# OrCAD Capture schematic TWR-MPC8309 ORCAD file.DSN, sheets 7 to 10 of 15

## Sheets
7 P07:ETH PHYs & RJ45: size C; title: ETH PHYs & RJ45
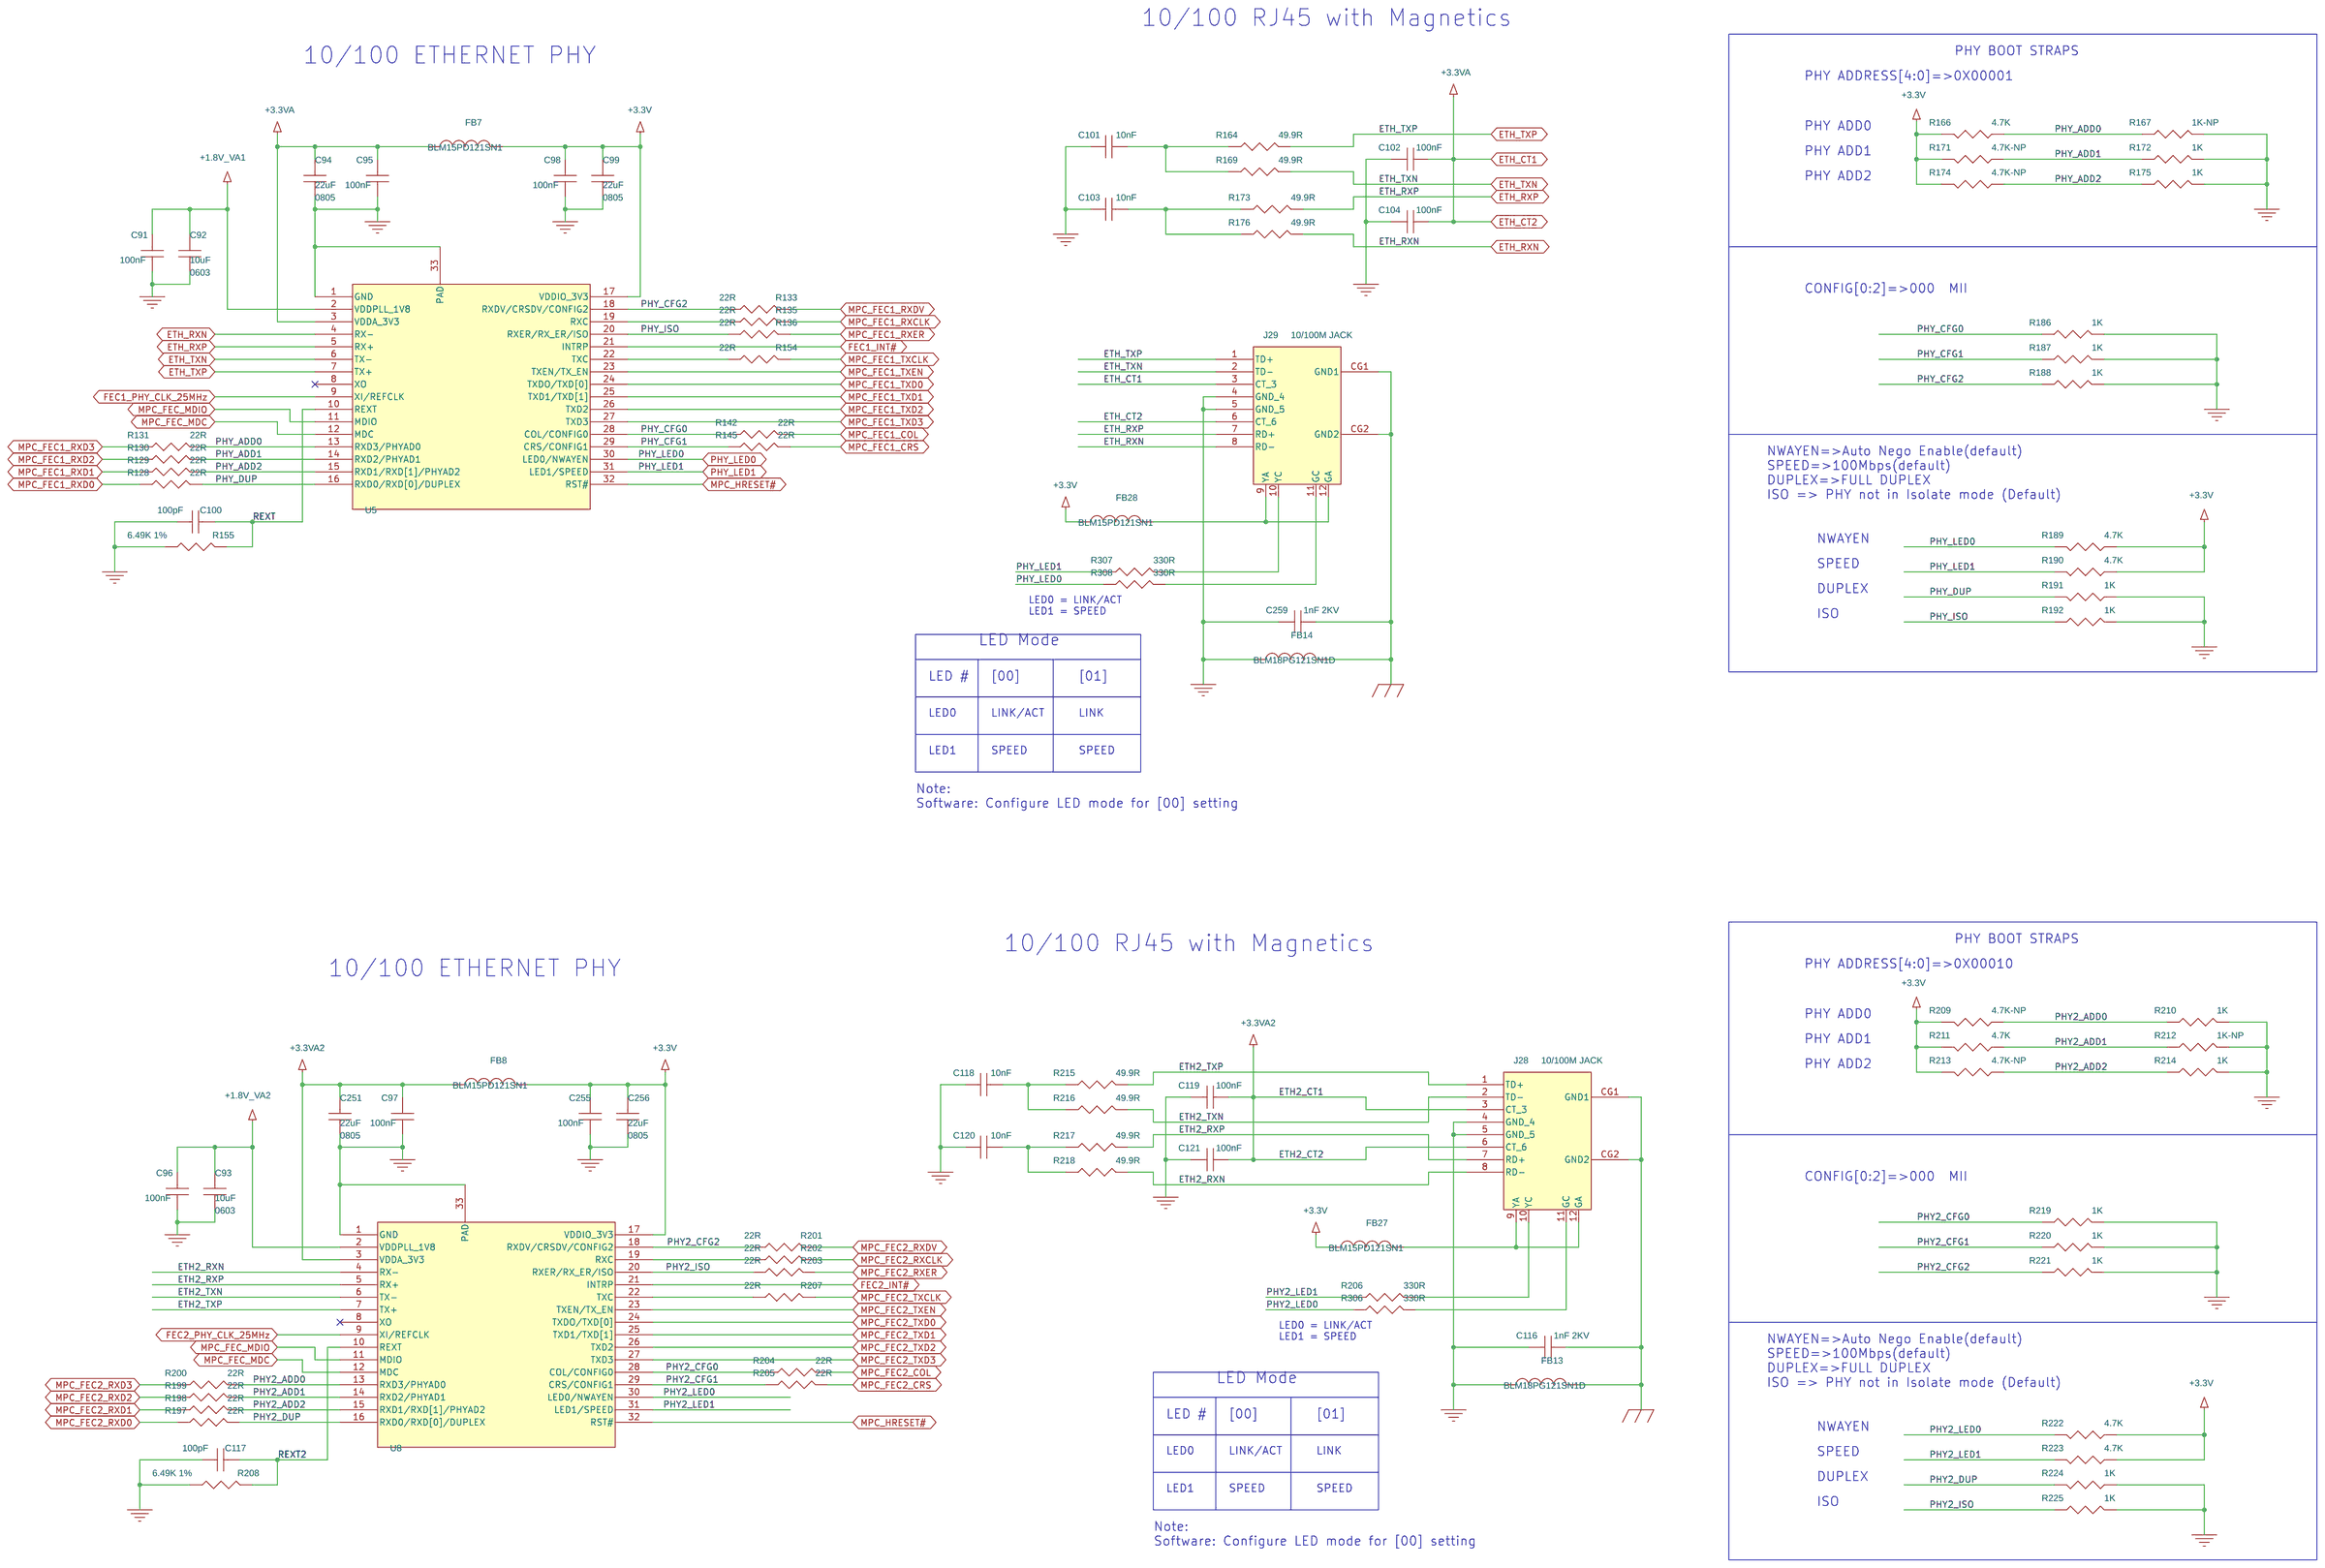
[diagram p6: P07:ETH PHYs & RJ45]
8 P02:Reset, Clock & Switch: size C; title: Reset, Clock and Switch
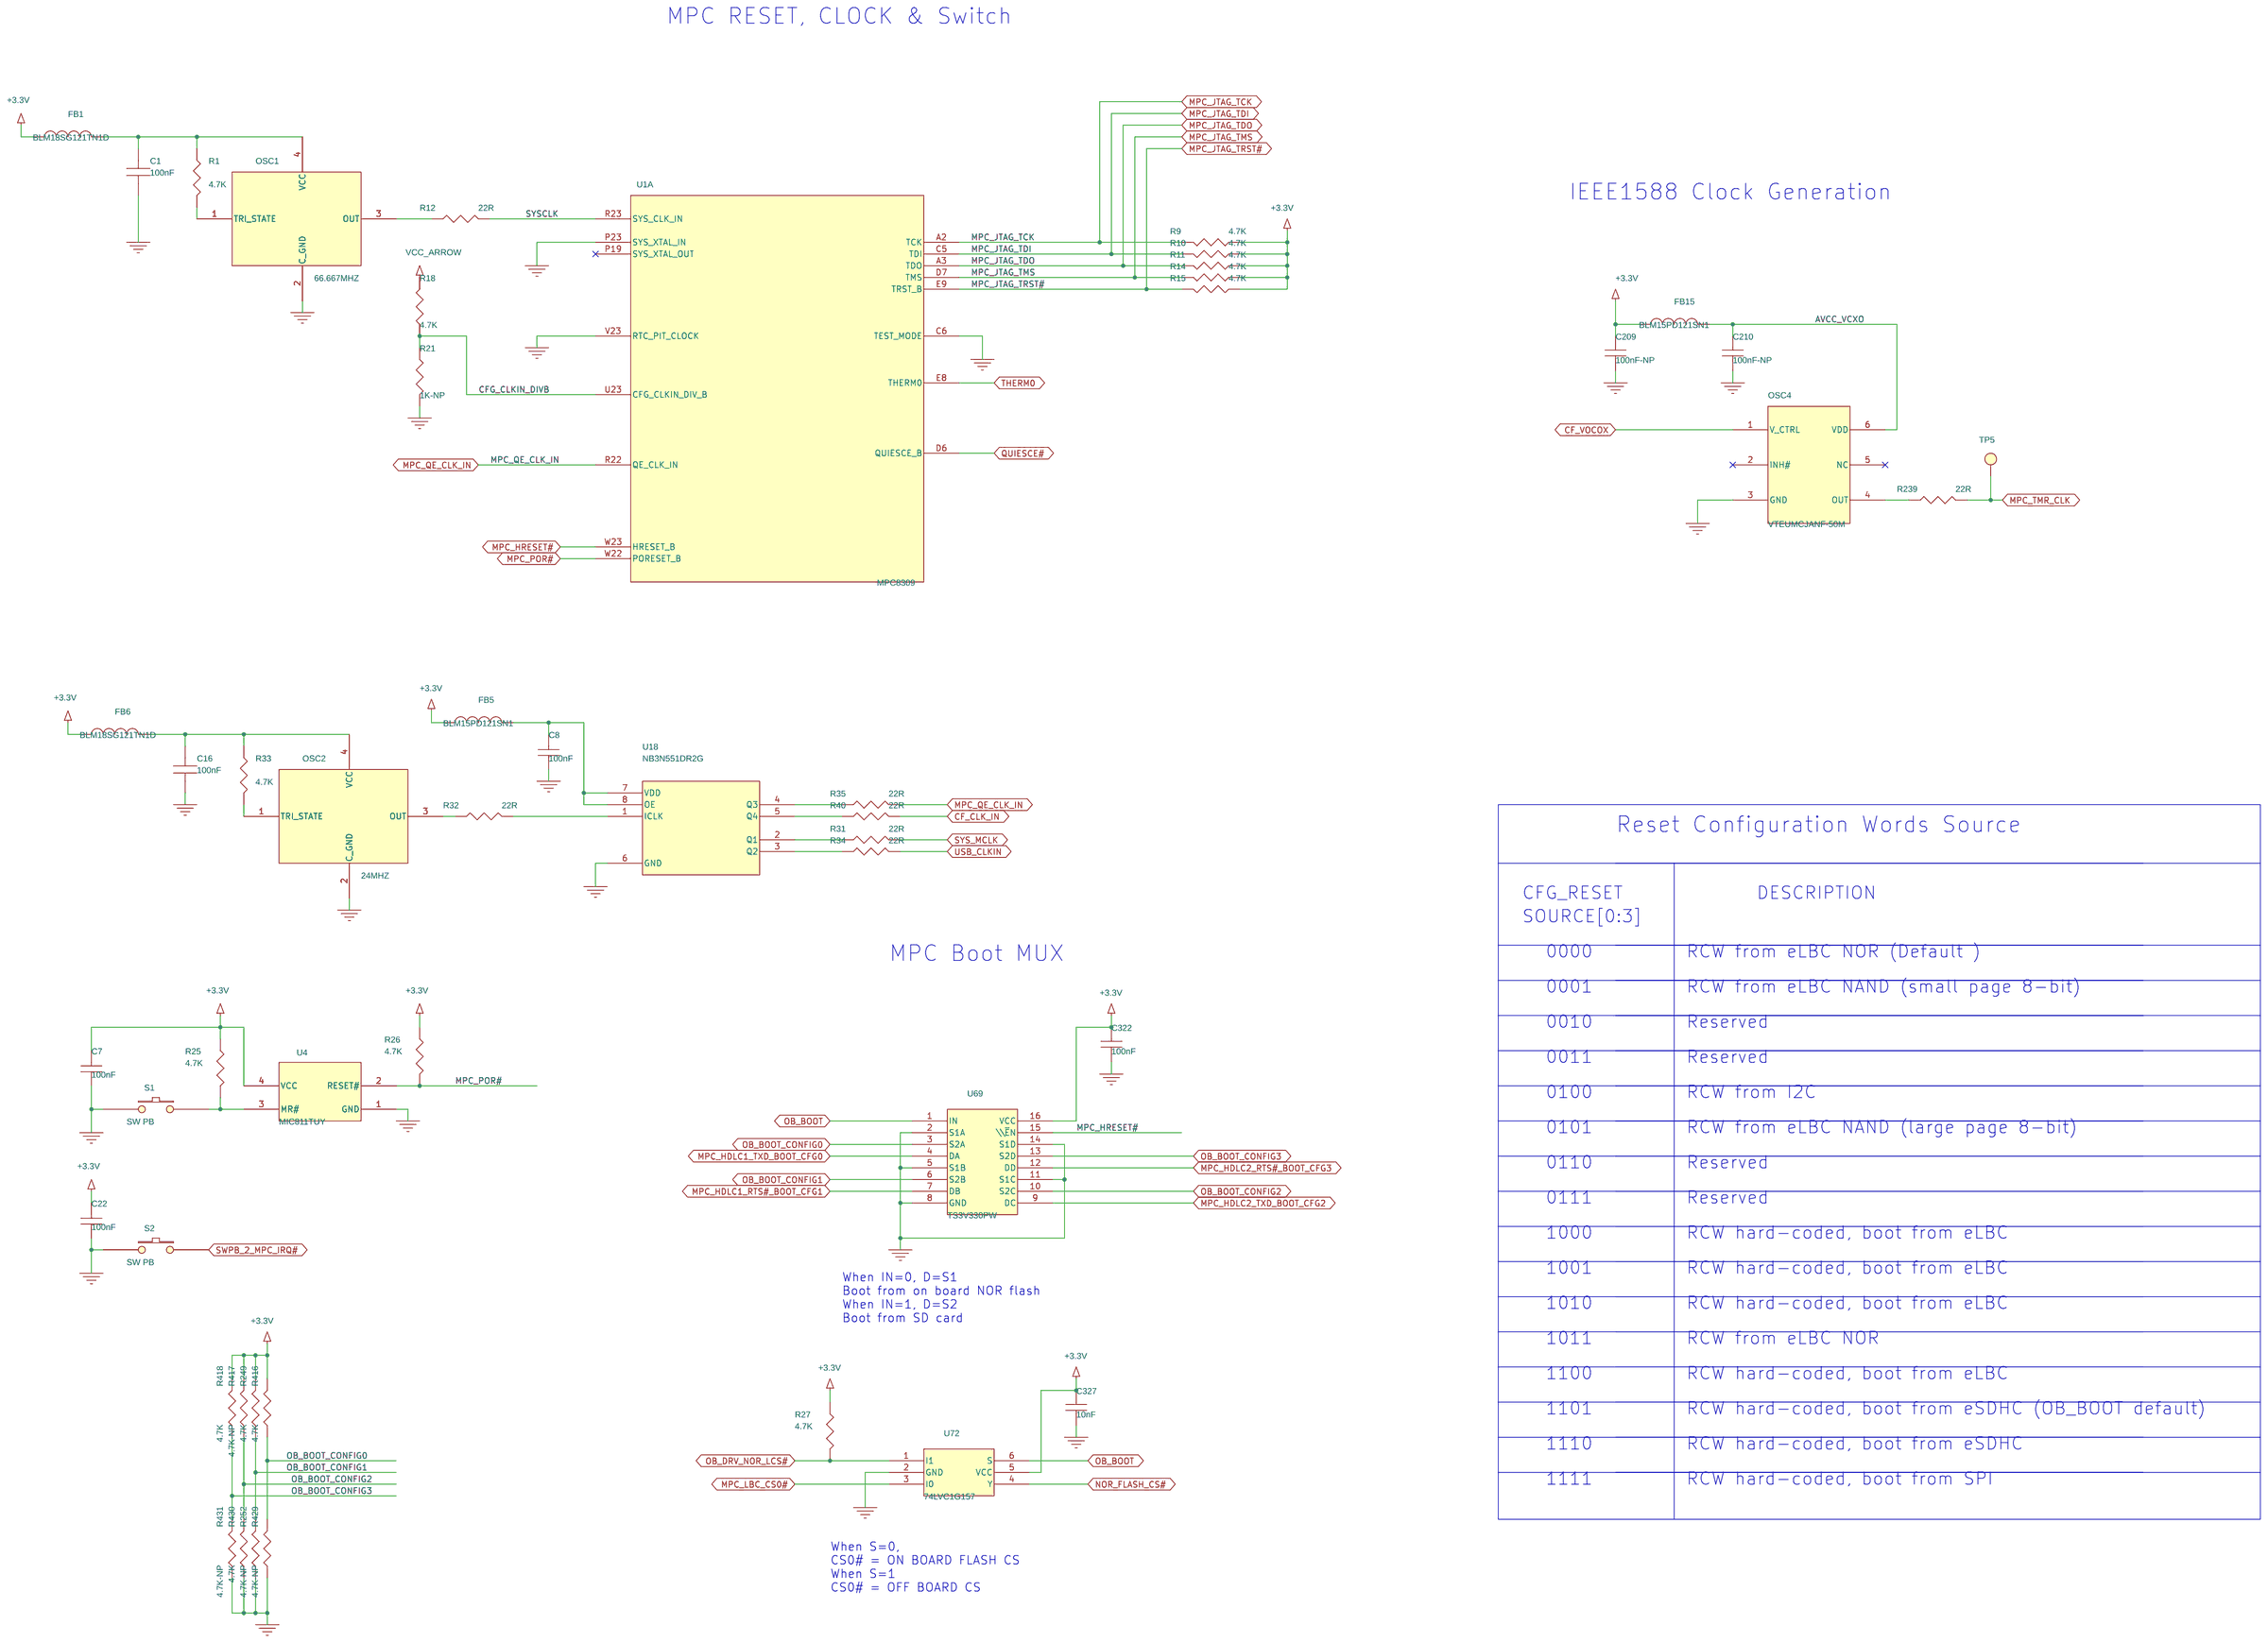
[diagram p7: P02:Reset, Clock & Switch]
9 P08:USB Interface & USB PHY: size C; title: USB Interface and USB PHY
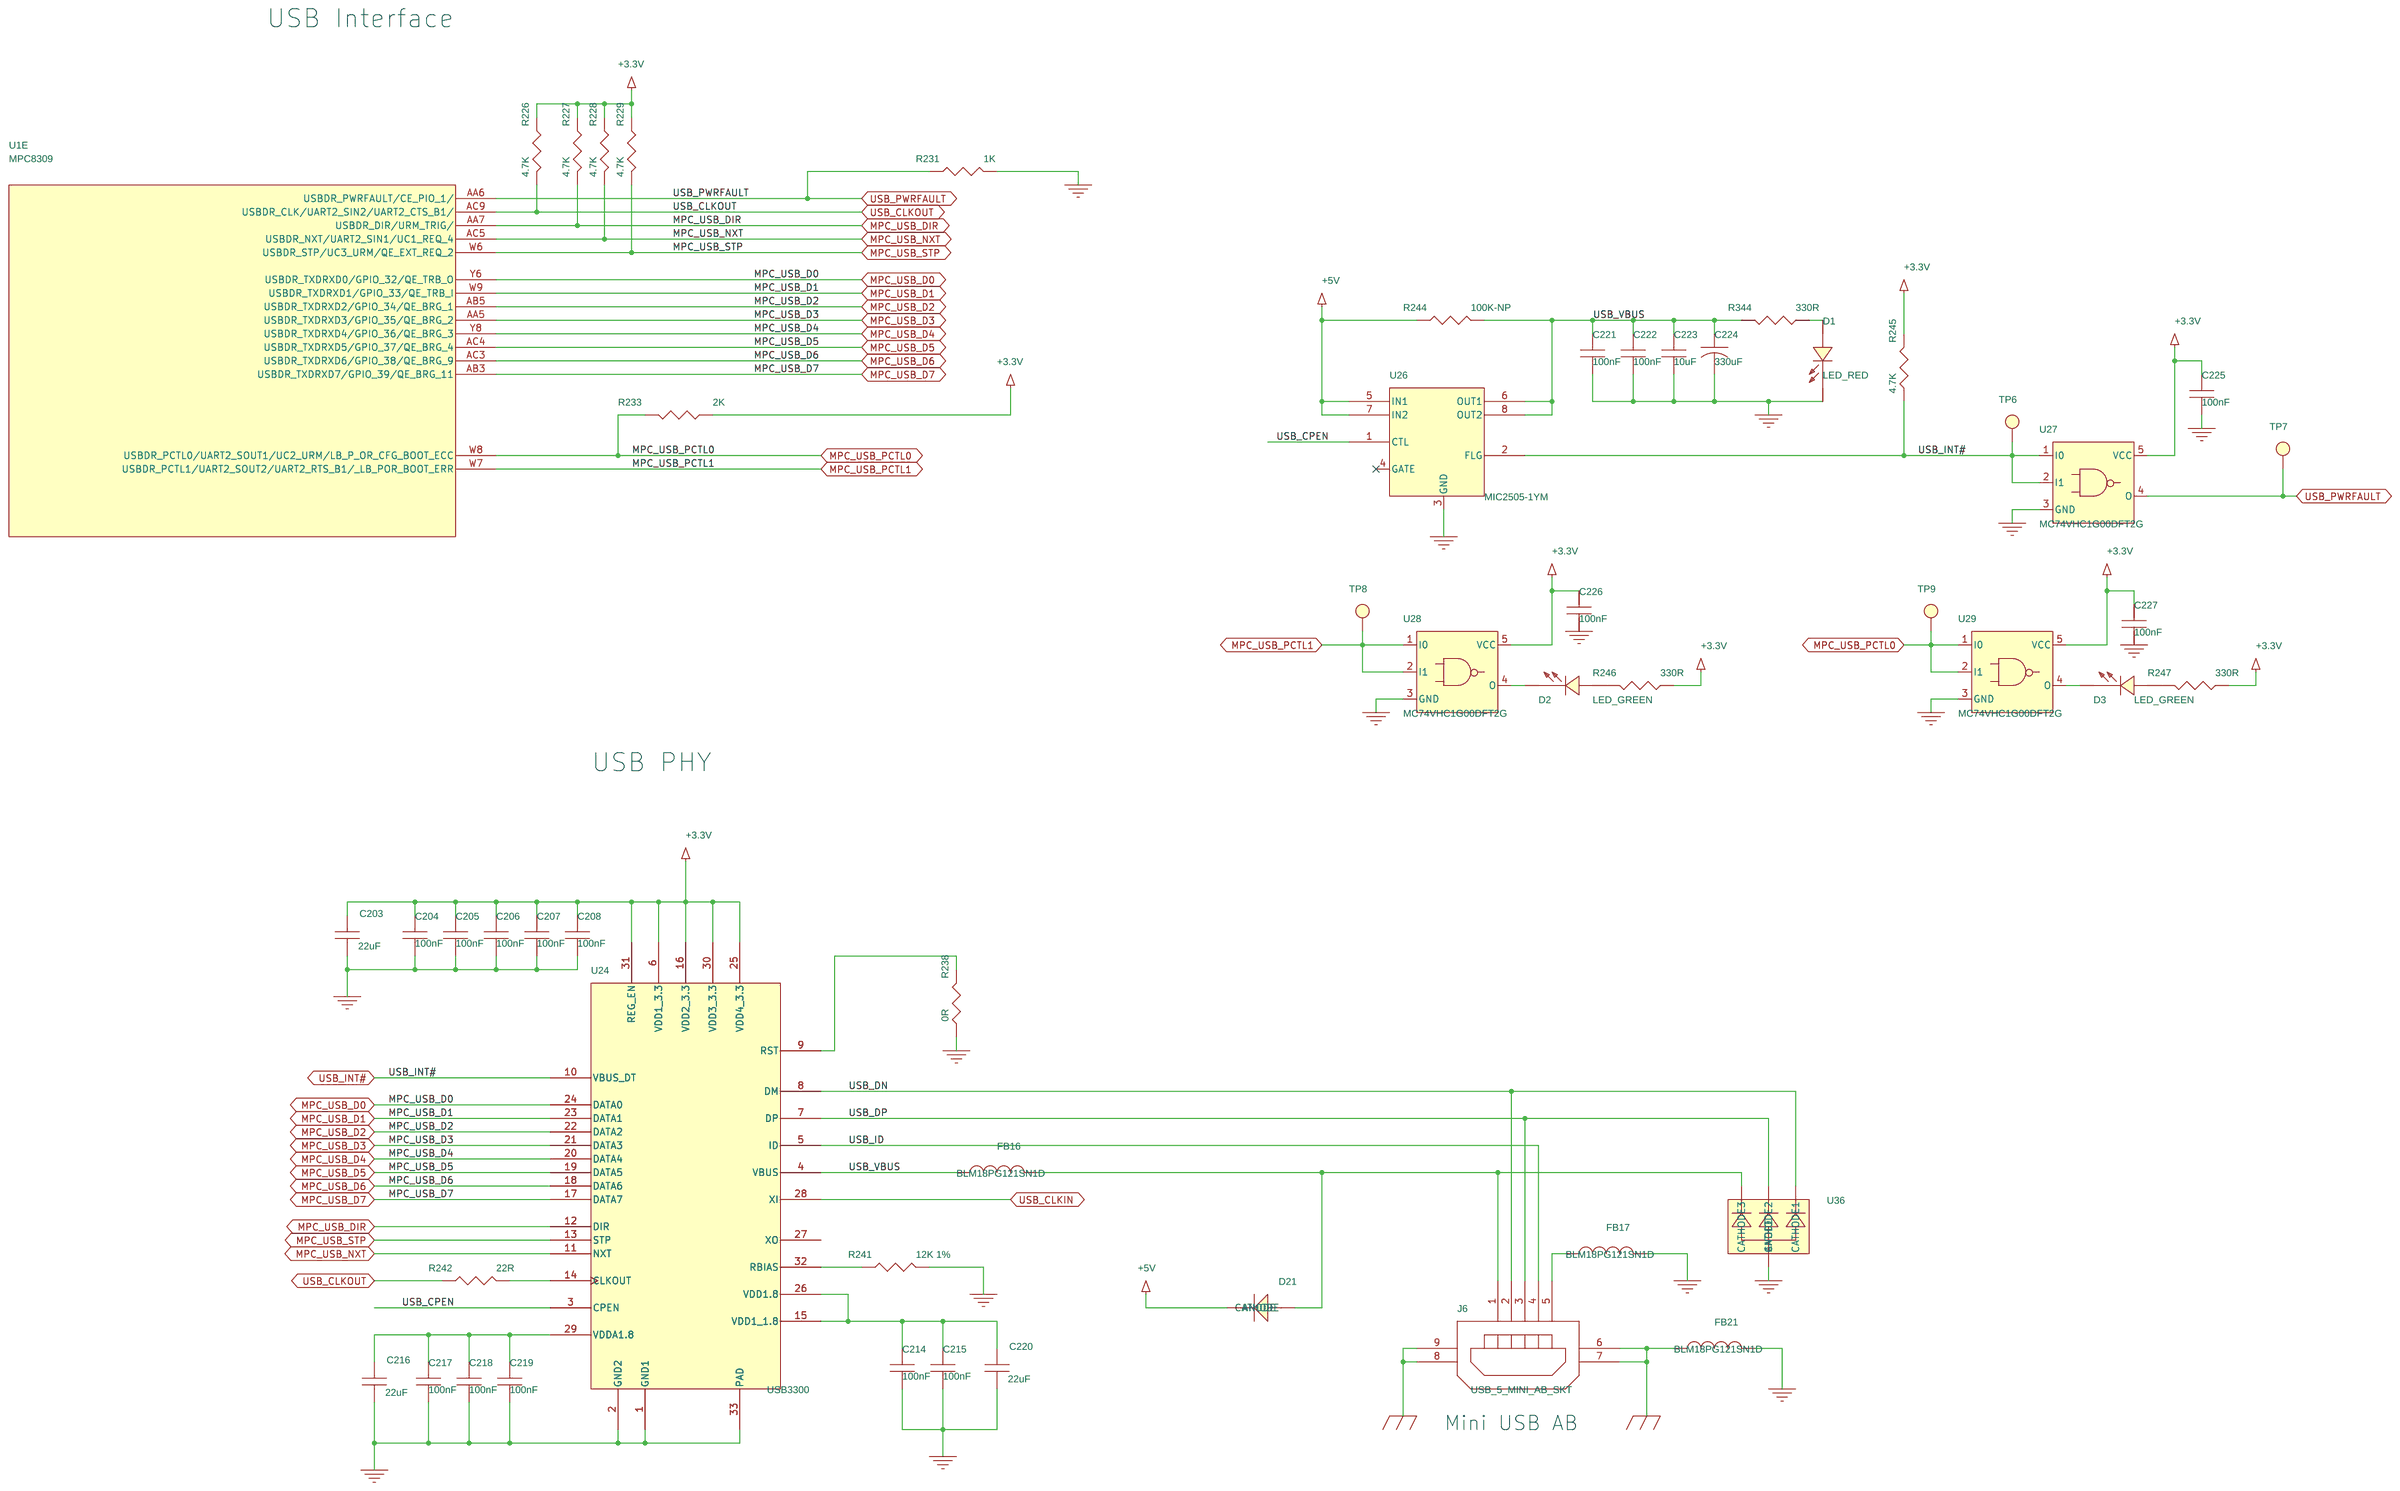
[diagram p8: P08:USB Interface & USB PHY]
10 P03:DDR2 & NOR Flash Memory: size C; title: DDR2 and NOR Flash Memory
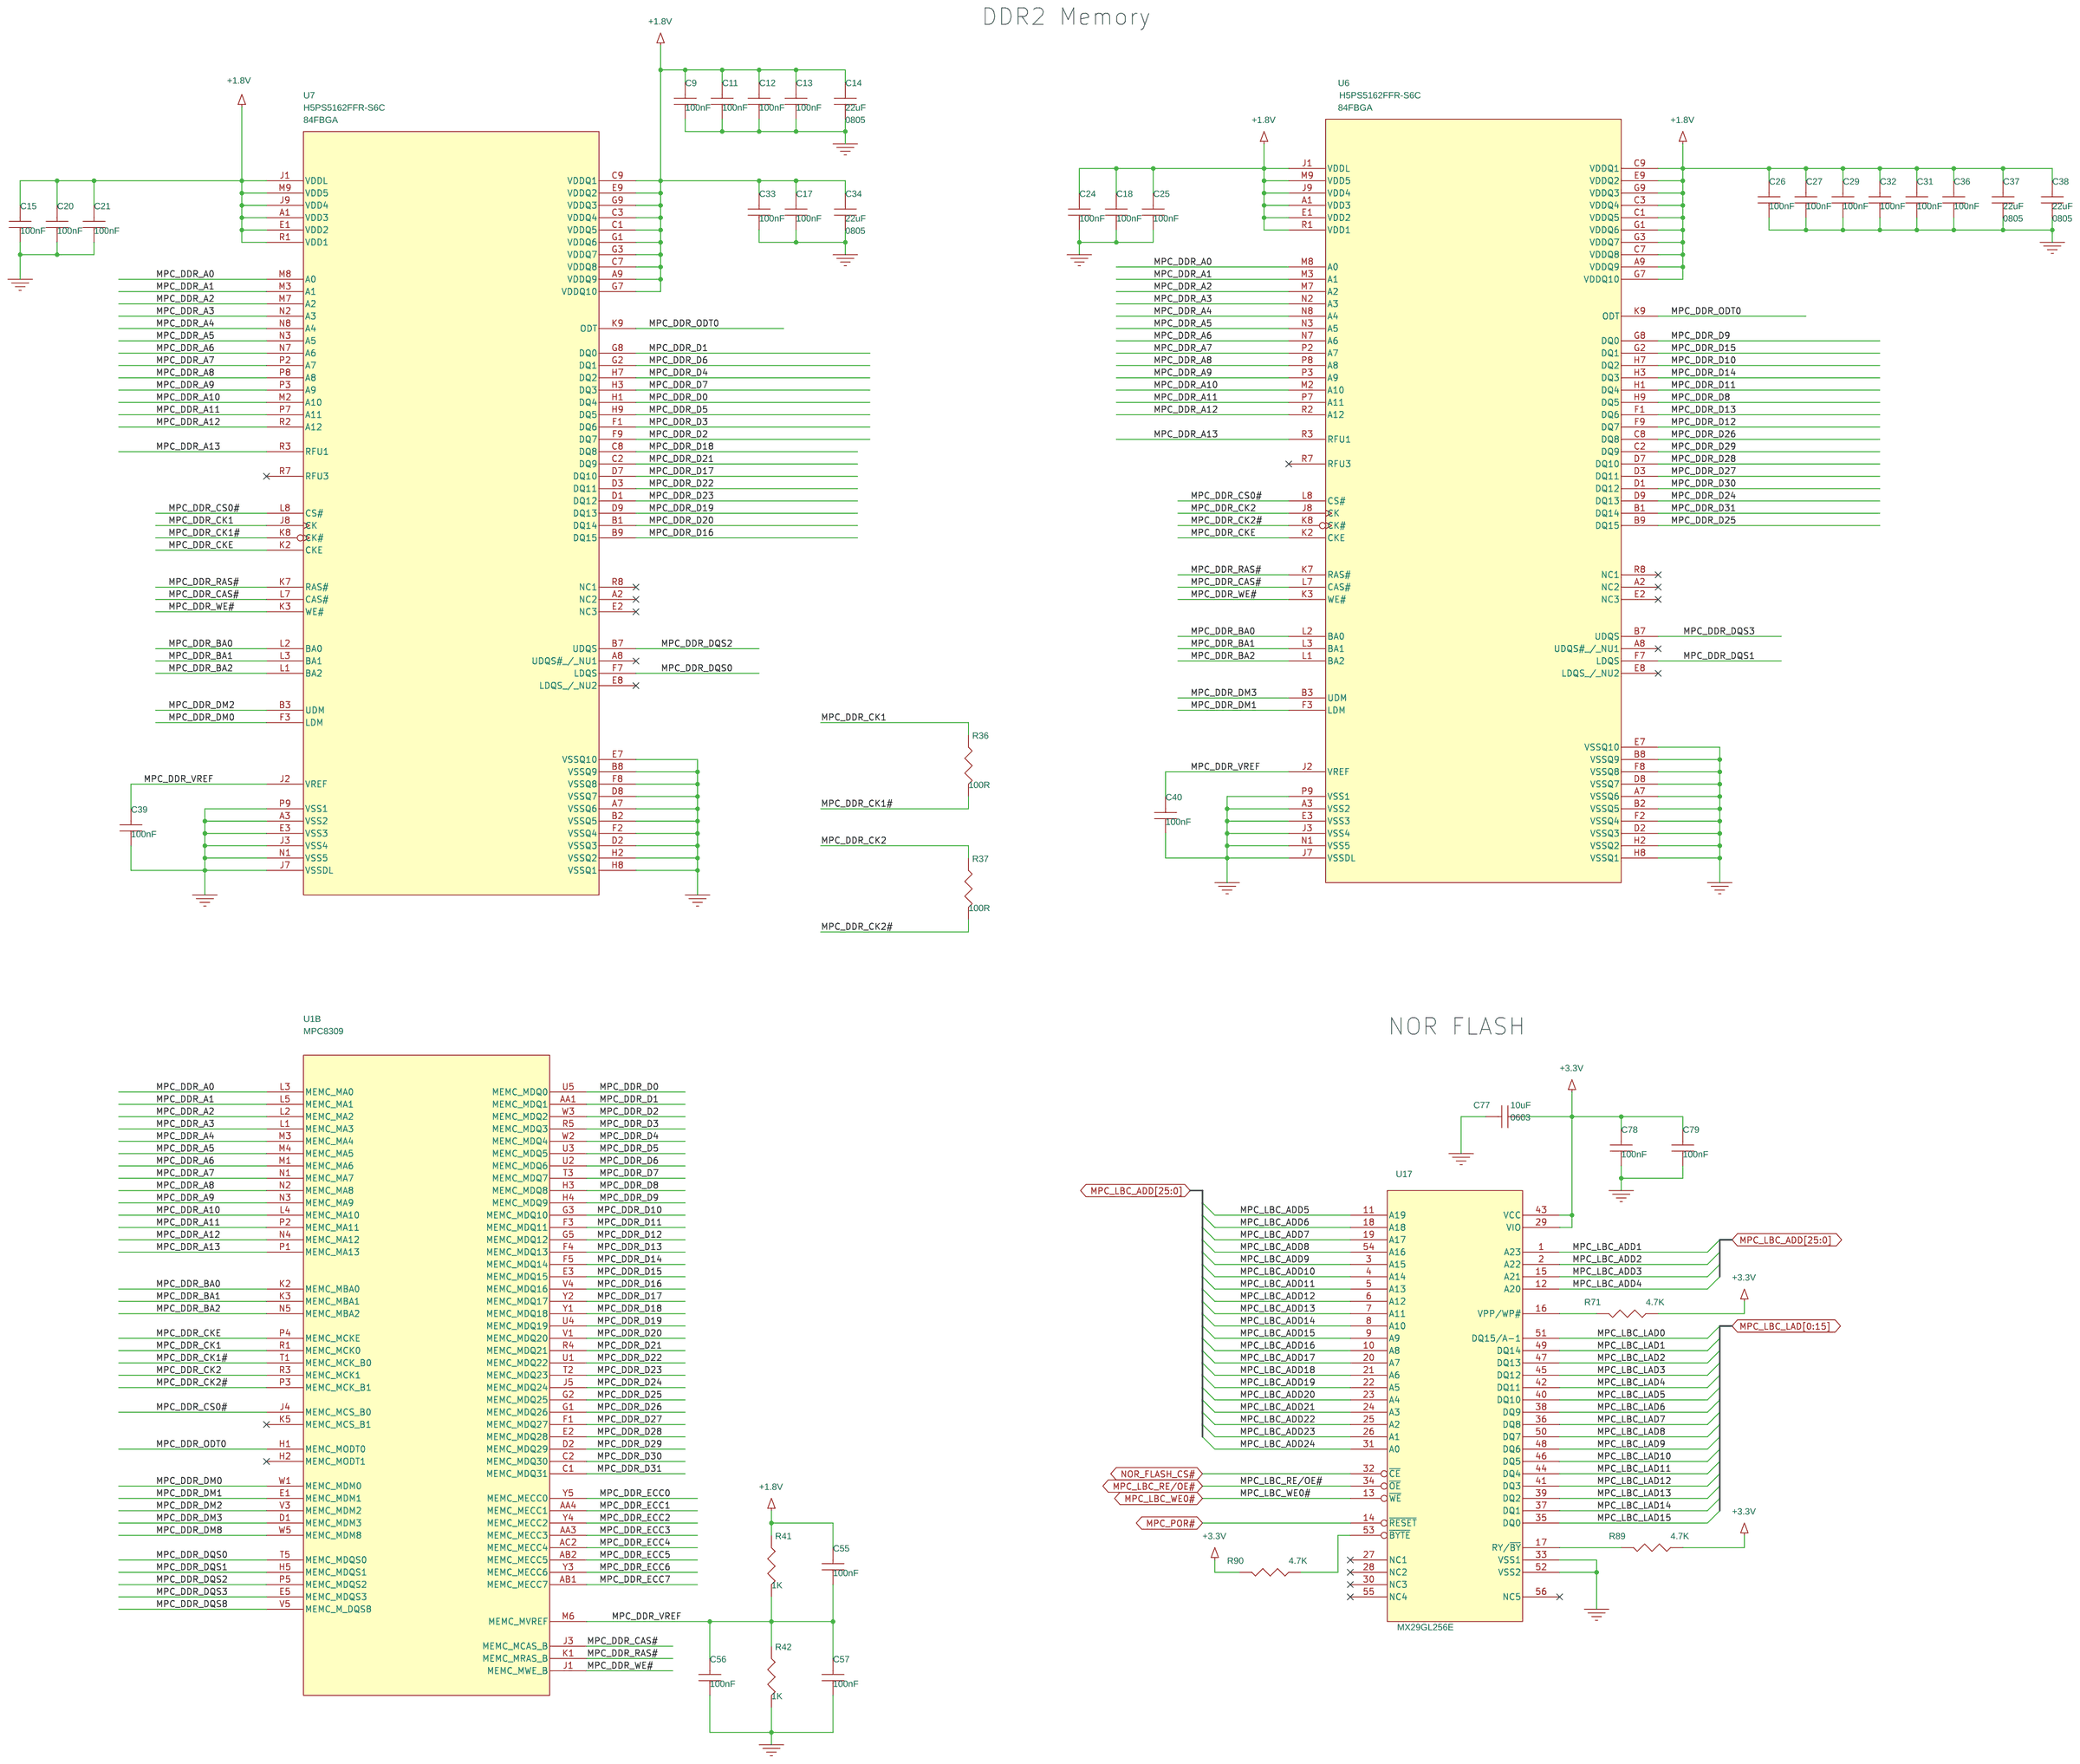
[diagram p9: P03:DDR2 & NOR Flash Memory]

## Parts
sheet P02:Reset, Clock & Switch
C1  100nF  [CC0402_CR]
C7  100nF  [CC0402_CR]
C8  100nF  [CC0402_CR]
C16  100nF  [CC0402_CR]
C22  100nF  [CC0402_CR]
C209  100nF-NP  [CC0402_CR]
C210  100nF-NP  [CC0402_CR]
C322  100nF  [CC0603]
C327  10nF  [CC0402_CR]
FB1  BLM18SG121TN1D  [L0603]
FB5  BLM15PD121SN1  [L0402]
FB6  BLM18SG121TN1D  [L0603]
FB15  BLM15PD121SN1  [L0402]
OSC1  66.667MHZ  [C30H]
OSC2  24MHZ  [C30H]
OSC4  VTEUMCJANF-50M  [VCXO_SMD]
R1  4.7K  [R0402_CR]
R9  4.7K  [R0402_CR]
R10  4.7K  [R0402_CR]
R11  4.7K  [R0402_CR]
R12  22R  [R0402_CR]
R14  4.7K  [R0402_CR]
R15  4.7K  [R0402_CR]
R18  4.7K  [R0402_CR]
R21  1K-NP  [R0402_CR]
R25  4.7K  [R0402_CR]
R26  4.7K  [R0402_CR]
R27  4.7K  [R0402_CR]
R31  22R  [R0402_CR]
R32  22R  [R0402_CR]
R33  4.7K  [R0402_CR]
R34  22R  [R0402_CR]
R35  22R  [R0402_CR]
R40  22R  [R0402_CR]
R239  22R  [R0402_CR]
R249  4.7K  [R0402_CR]
R252  4.7K-NP  [R0402_CR]
R416  4.7K  [R0402_CR]
R417  4.7K-NP  [R0402_CR]
R418  4.7K  [R0402_CR]
R429  4.7K-NP  [R0402_CR]
R430  4.7K  [R0402_CR]
R431  4.7K-NP  [R0402_CR]
S1  SW PB  [SMD_SW]
S2  SW PB  [SMD_SW]
TP5  TP  [SMD_TP]
U4  MIC811TUY  [SOT143A]
U18  NB3N551DR2G  [SOIC127P600X173-8N]
U69  TS3V330PW  [TSSOP16]
U72  74LVC1G157  [SOT363]
sheet P03:DDR2 & NOR Flash Memory
C9  100nF  [CC0402_CR]
C11  100nF  [CC0402_CR]
C12  100nF  [CC0402_CR]
C13  100nF  [CC0402_CR]
C14  22uF  [CC0805]
C15  100nF  [CC0402_CR]
C17  100nF  [CC0402_CR]
C18  100nF  [CC0402_CR]
C20  100nF  [CC0402_CR]
C21  100nF  [CC0402_CR]
C24  100nF  [CC0402_CR]
C25  100nF  [CC0402_CR]
C26  100nF  [CC0402_CR]
C27  100nF  [CC0402_CR]
C29  100nF  [CC0402_CR]
C31  100nF  [CC0402_CR]
C32  100nF  [CC0402_CR]
C33  100nF  [CC0402_CR]
C34  22uF  [CC0805]
C36  100nF  [CC0402_CR]
C37  22uF  [CC0805]
C38  22uF  [CC0805]
C39  100nF  [CC0402_CR]
C40  100nF  [CC0402_CR]
C55  100nF  [CC0402_CR]
C56  100nF  [CC0402_CR]
C57  100nF  [CC0402_CR]
C77  10uF  [CC0603]
C78  100nF  [CC0402_CR]
C79  100nF  [CC0402_CR]
R36  100R  [R0402_CR]
R37  100R  [R0402_CR]
R41  1K  [R0402_CR]
R42  1K  [R0402_CR]
R71  4.7K  [R0402_CR]
R89  4.7K  [R0402_CR]
R90  4.7K  [R0402_CR]
U6  H5PS5162FFR-S6C  [fbga_84_0p8_8x12p5]
U7  H5PS5162FFR-S6C  [fbga_84_0p8_8x12p5]
U17  MX29GL256E  [TSOP56]
sheet P07:ETH PHYs & RJ45
C91  100nF  [CC0402_CR]
C92  10uF  [CC0603]
C93  10uF  [CC0603]
C94  22uF  [CC0805]
C95  100nF  [CC0402_CR]
C96  100nF  [CC0402_CR]
C97  100nF  [CC0402_CR]
C98  100nF  [CC0402_CR]
C99  22uF  [CC0805]
C100  100pF  [CC0603]
C101  10nF  [CC0402_CR]
C102  100nF  [CC0402_CR]
C103  10nF  [CC0402_CR]
C104  100nF  [CC0402_CR]
C116  1nF 2KV  [C1206]
C117  100pF  [CC0603]
C118  10nF  [CC0402_CR]
C119  100nF  [CC0402_CR]
C120  10nF  [CC0402_CR]
C121  100nF  [CC0402_CR]
C251  22uF  [CC0805]
C255  100nF  [CC0402_CR]
C256  22uF  [CC0805]
C259  1nF 2KV  [C1206]
FB7  BLM15PD121SN1  [L0402]
FB8  BLM15PD121SN1  [L0402]
FB13  BLM18PG121SN1D  [L0603]
FB14  BLM18PG121SN1D  [L0603]
FB27  BLM15PD121SN1  [L0402]
FB28  BLM15PD121SN1  [L0402]
J28  10/100M JACK  [RJ45_LED_MAG]
J29  10/100M JACK  [RJ45_LED_MAG]
R128  22R  [R0402_CR]
R129  22R  [R0402_CR]
R130  22R  [R0402_CR]
R131  22R  [R0402_CR]
R133  22R  [R0402_CR]
R135  22R  [R0402_CR]
R136  22R  [R0402_CR]
R142  22R  [R0402_CR]
R145  22R  [R0402_CR]
R154  22R  [R0402_CR]
R155  6.49K 1%  [R0603B]
R164  49.9R  [R0402_CR]
R166  4.7K  [R0402_CR]
R167  1K-NP  [R0402_CR]
R169  49.9R  [R0402_CR]
R171  4.7K-NP  [R0402_CR]
R172  1K  [R0402_CR]
R173  49.9R  [R0402_CR]
R174  4.7K-NP  [R0402_CR]
R175  1K  [R0402_CR]
R176  49.9R  [R0402_CR]
R186  1K  [R0402_CR]
R187  1K  [R0402_CR]
R188  1K  [R0402_CR]
R189  4.7K  [R0402_CR]
R190  4.7K  [R0402_CR]
R191  1K  [R0402_CR]
R192  1K  [R0402_CR]
R197  22R  [R0402_CR]
R198  22R  [R0402_CR]
R199  22R  [R0402_CR]
R200  22R  [R0402_CR]
R201  22R  [R0402_CR]
R202  22R  [R0402_CR]
R203  22R  [R0402_CR]
R204  22R  [R0402_CR]
R205  22R  [R0402_CR]
R206  330R  [R0402_CR]
R207  22R  [R0402_CR]
R208  6.49K 1%  [R0603B]
R209  4.7K-NP  [R0402_CR]
R210  1K  [R0402_CR]
R211  4.7K  [R0402_CR]
R212  1K-NP  [R0402_CR]
R213  4.7K-NP  [R0402_CR]
R214  1K  [R0402_CR]
R215  49.9R  [R0402_CR]
R216  49.9R  [R0402_CR]
R217  49.9R  [R0402_CR]
R218  49.9R  [R0402_CR]
R219  1K  [R0402_CR]
R220  1K  [R0402_CR]
R221  1K  [R0402_CR]
R222  4.7K  [R0402_CR]
R223  4.7K  [R0402_CR]
R224  1K  [R0402_CR]
R225  1K  [R0402_CR]
R306  330R  [R0402_CR]
R307  330R  [R0402_CR]
R308  330R  [R0402_CR]
U5  KSZ8041NL Rev4  [qfn32_5x5]
U8  KSZ8041NL Rev4  [qfn32_5x5]
sheet P08:USB Interface & USB PHY
C203  22uF  [CC0805]
C204  100nF  [CC0402_CR]
C205  100nF  [CC0402_CR]
C206  100nF  [CC0402_CR]
C207  100nF  [CC0402_CR]
C208  100nF  [CC0402_CR]
C214  100nF  [CC0402_CR]
C215  100nF  [CC0402_CR]
C216  22uF  [CC0805]
C217  100nF  [CC0402_CR]
C218  100nF  [CC0402_CR]
C219  100nF  [CC0402_CR]
C220  22uF  [CC0805]
C221  100nF  [CC0402_CR]
C222  100nF  [CC0402_CR]
C223  10uF  [CC0805]
C224  330uF  [C7343]
C225  100nF  [CC0402_CR]
C226  100nF  [CC0402_CR]
C227  100nF  [CC0402_CR]
D1  LED_RED  [LED0603]
D2  LED_GREEN  [LED0603]
D3  LED_GREEN  [LED0603]
D21  RB060M_30  [SOD_123]
FB16  BLM18PG121SN1D  [L0603]
FB17  BLM18PG121SN1D  [L0603]
FB21  BLM18PG121SN1D  [L0603]
J6  USB_5_MINI_AB_SKT  [USB-mini-ab]
R226  4.7K  [R0402_CR]
R227  4.7K  [R0402_CR]
R228  4.7K  [R0402_CR]
R229  4.7K  [R0402_CR]
R231  1K  [R0402_CR]
R233  2K  [R0402_CR]
R238  0R  [R0402_CR]
R241  12K 1%  [R0603B]
R242  22R  [R0402_CR]
R244  100K-NP  [R0603B]
R245  4.7K  [R0402_CR]
R246  330R  [R0402_CR]
R247  330R  [R0402_CR]
R344  330R  [R0402_CR]
TP6  TP  [SMD_TP]
TP7  TP  [SMD_TP]
TP8  TP  [SMD_TP]
TP9  TP  [SMD_TP]
U24  USB3300  [qfn32_5x5]
U26  MIC2505-1YM  [SOIC127P600X173-8N]
U27  MC74VHC1G00DFT2G  [SOT353]
U28  MC74VHC1G00DFT2G  [SOT353]
U29  MC74VHC1G00DFT2G  [SOT353]
U36  SP0503B  [sot143]
sheet P14:MPC Decoupling
U1  MPC8309  [MAPBGA489_80p]  (sections A,B,C,D,E,F,G,H,I)

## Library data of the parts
C1 C16 = Cap_bulk_nonpol_1: Cap, 0.01uF, 10%, Cer-X5R, 16V, SMD, Size 0402; Material: Cer-X7R; Mfg: AVX; Mfg Part No: 0402YD103MAT2A; ROOM: ETH; Volts: 16V
C7-C9 C11-C13 C15 C17 C18 C20-C22 C24-C27 C29 C31-C33 C36 C39 C40 C55-C57 C78 C79 C91 C95-C98 C102 C104 C119 C121 C255 = CAP_NP: Mfg: Kemet; Mfg Part#: C0402C104K8PACTU; Oper. Temp. Range: -55°C ~ 85°C; Package: 0402; Price @ 100 pcs: 0.014; Price @ 10K: 0.0060; Price @ 1K: 0.0066; RoHS Compliant?: Yes; Specifications: CAP .10UF 10V CERAMIC X5R 0402; Vendor: Digikey; Vendor Part#: 399-3027-1-ND
C209 C210 = CAP_NP: Mfg: Kemet; Mfg Part#: C0402C104K8PACTU; Mounting: NU; Package: 0402; RoHS Compliant?: Yes; Specifications: CAP .10UF 10V CERAMIC X5R 0402
C322 C327 = CAP_NP_1: CLASS: Discrete
FB1 FB5-FB8 FB13-FB17 FB21 FB27 FB28 = INDUCTOR_0: Ferrite Bead, 2A, 140 OHMS, 1GHZ, SMD0603; Cost_Proto: 0.25; Cost_Vol: 0.14; Mfg: Murata; Mfg Part No: BLM18EG101TN1; Room: ETH
OSC1 OSC2 = Osc_EC2600TS-33.333M: ITTI,OSC, C30H25-50.000-12, 3.3V, SMD; Mfg: ITTI; Mfg Part No: C30H25-50.000-12; ROOM: ETH
OSC4 = VCXO_SMD_0: Mfg: Taitien/CTS; Mfg Part#: VTEUMCJANF-50M/357LB3I040M0000; Mounting: NU; Package: OSC 6 pin; RoHS Compliant?: Yes; Specifications: OSC VCXO 40.0000 MHZ 5X7MM SMD
R1 R33 = Res: Res, 4.7K, 5%, Chip, 0.063W, SMD, Size 0402; GDA Part No: GRX-R-00000587; Mfg: KOA; Mfg Part No: RK73B1ETTP472J; Part Number: GRX-R-00000587; ROOM: ETH; Sub_Type: Chip; Tolerance: 5%
R9-R11 R14 R15 R18 R71 R89 R90 R166 R189-R191 R211 R222-R224 R226-R229 R249 R252 R416-R418 R429-R431 = RESISTOR: Mfg: Yageo; Mfg Part#: RC0402JR-074K7L; Oper. Temp. Range: -55°C ~ 85°C; Package: 0402; Price @ 100 pcs: 0.0066; Price @ 10K: 0.00213; Price @ 1K: 0.035; RoHS Compliant?: Yes; Specifications: RES 4.7K OHM 1/16W 5% 0402 SMD; Vendor: Digikey; Vendor Part#: 311-4.7KJRCT-ND
R12 R32 = RESISTOR: Mfg: Yageo; Mfg Part#: RC0402FR-0722RL; Oper. Temp. Range: -55°C ~ 85°C; Package: 0402; Price @ 100 pcs: 0.066; Price @ 10K: 0.036; Price @ 1K: 0.00243; RoHS Compliant?: Yes; Specifications: RES 22.0 OHM 1/16W 1% 0402 SMD; Vendor: Digikey; Vendor Part#: 311-22.0LRCT-ND
R21 R167 R212 = RESISTOR: Mfg: Yageo; Mfg Part#: RC0402FR-071KL; Mounting: NU; Oper. Temp. Range: -55°C ~ 85°C; Package: 0402; Price @ 100 pcs: 0.036; Price @ 10K: 0.00242; Price @ 1K: 0.0142; RoHS Compliant?: Yes; Specifications: RES 1.00K OHM 1/16W 1% 0402 SMD; Vendor: Digikey; Vendor Part#: 311-1.00KLRCT-ND
R25-R27 = R_4: RES MF 4.7K 1/16W 5% 0402; AGILE_PN: 470-75626; CAD_APPROVED: Yes; CLASS: discrete; MFG_NAME01: SMEC; MFG_PN01: RC73L2Z472JTF; ROHS: Yes; Tolerance: 5%
R31 R34 R35 R40 R128-R131 R133 R135 R136 R142 R145 R154 R197-R205 R207 = RESISTOR: Mfg: Yageo; Mfg Part#: RC0402FR-0722RL; Package: 0402; Price @ 100 pcs: 0.066; Price @ 10K: 0.036; Price @ 1K: 0.00243; RoHS Compliant?: Yes; Specifications: RES 22.0 OHM 1/16W 1% 0402 SMD; Vendor: Digikey; Vendor Part#: 311-22.0LRCT-ND
R239 = RESISTOR: Mfg: Yageo; Mfg Part#: RC0402FR-0722RL; Mounting: NU; Package: 0402; RoHS Compliant?: Yes; Specifications: RES 22.0 OHM 1/16W 1% 0402 SMD
S1 S2 = SW_PUSHBUTTON_0: SW SPST PB 50MA 12V SMT; AGILE_PN: 510-77693; CAD_APPROVED: Yes; CLASS: IO; HEIGHT: 1.7MM; MFG_NAME01: ELITE TECHNOLOGY (SUZHOU) CO.,LTD; MFG_PN01: ELTSK-52N-T/R-H; ROHS: Yes
TP5-TP9 = TP: RoHS Compliant?: Yes
U4 = MAX811TEUS: IC VSUP THRESHOLD 3.08V SOT143; AGILE_PN: 312-79609; CAD_APPROVED: Yes; CLASS: IC; HEIGHT: 1.22 MM; MFG_NAME01: MAXIM; MFG_PN01: MAX811TEUS+; ROHS: Yes
U18 = IC_CLKBUF_1to_4_NB3N551: Mfg: ON Semiconductor; Vendor: MOUSER; Vendor Part#: 863-NB3N551DR2G
U69 = TS3V330PW
U72 = 74LVC1G157
C14 C34 C37 C38 C94 C99 C251 C256 = CAP_NP: Mfg: Taiyo Yuden; Mfg Part#: LMK212BJ226MG-T; Oper. Temp. Range: -55°C ~ 85°C; Package: 0805; Price @ 100 pcs: 0.42; Price @ 10K: 0.168; Price @ 1K: 0.30; RoHS Compliant?: Yes; Specifications: CAP CER 22UF 10V X5R 0805; Vendor: Digikey; Vendor Part#: 587-1958-1-ND
C77 C92 C93 C100 C117 = CAP_NP: Mfg: Kemet; Mfg Part#: C0603C106M9PACTU; Oper. Temp. Range: -55°C ~ 85°C; Package: 0603; Price @ 100 pcs: 0.312; Price @ 10K: 0.105; Price @ 1K: 0.1248; RoHS Compliant?: Yes; Specifications: CAP CER 10UF 6.3V X5R 0603; Vendor: Digikey; Vendor Part#: 399-5504-1-ND
R36 R37 R41 R42 R172 R175 R186-R188 R192 R210 R214 R219-R221 R225 R231 = RESISTOR: Mfg: Yageo; Mfg Part#: RC0402FR-071KL; Oper. Temp. Range: -55°C ~ 85°C; Package: 0402; Price @ 100 pcs: 0.036; Price @ 10K: 0.00242; Price @ 1K: 0.0142; RoHS Compliant?: Yes; Specifications: RES 1.00K OHM 1/16W 1% 0402 SMD; Vendor: Digikey; Vendor Part#: 311-1.00KLRCT-ND
U6 U7 = IC_DDR2_x16_1Gb_84BGA: Mfg: Micron; Mfg Part#: MT47H64M16HR-3 IT:H; Oper. Temp. Range: -40°C ~ 85°C; Package: 84FBGA; Price @ 100 pcs: 5.50; Price @ 10K: 5.0; Price @ 1K: 5.0; RoHS Compliant?: Yes; Specifications: 1Gb DDR2 SDRAM, x16; Vendor: Micron; Vendor Part#: MT47H64M16HR-3 IT:H
U17 = MX29GL256E
C101 C103 C118 C120 = CAP_NP: Mfg: Yageo; Mfg Part#: CC0402KRX7R9BB103; Oper. Temp. Range: -55°C ~ 125°C; Package: 0402; Price @ 100 pcs: 0.006; Price @ 10K: 0.0018; Price @ 1K: 0.00268; RoHS Compliant?: Yes; Specifications: CAP CERAMIC .01UF 50V X7R 0402; Vendor: Digikey; Vendor Part#: 311-1349-1-ND
C116 C259 = CAP_NP: Mfg: Kemet; Mfg Part#: C1206C102KGRACTU; Mounting: NU; Oper. Temp. Range: -55°C ~ 125°C; Package: 1206; Price @ 100 pcs: 0.0104; Price @ 10K: 0.004; Price @ 1K: 0.005; RoHS Compliant?: Yes; Specifications: CAP CER 1000PF 2000V X7R 1206; Vendor: Digikey; Vendor Part#: 399-4819-1-ND
J28 J29 = 10_100M_JACK
R155 R208 = RESISTOR: Mfg: Vishay/Dale; Mfg Part#: CRCW04026K65FKED; Package: 0402; Price @ 100 pcs: 0.072; Price @ 10K: 0.025; Price @ 1K: 0.008; RoHS Compliant?: Yes; Specifications: RES 6.65K OHM 1/16W 1% 0402 SMD; Vendor: Digikey; Vendor Part#: 541-6.65KLCT-ND
R164 R169 R173 R176 R215-R218 = RESISTOR: Mfg: Panasonic - ECG; Mfg Part#: ERJ-2RKF49R9X; Package: 0402; Price @ 100 pcs: 0.050; Price @ 10K: 0.023; Price @ 1K: 0.0085; RoHS Compliant?: Yes; Specifications: RES 49.9 OHM 1/16W 1% 0402 SMD; Vendor: Digikey; Vendor Part#: P49.9LTR-ND
R171 R174 R209 R213 = RESISTOR: Mfg: Yageo; Mfg Part#: RC0402JR-074K7L; Mounting: NU; Oper. Temp. Range: -55°C ~ 85°C; Package: 0402; Price @ 100 pcs: 0.0066; Price @ 10K: 0.00213; Price @ 1K: 0.035; RoHS Compliant?: Yes; Specifications: RES 4.7K OHM 1/16W 5% 0402 SMD; Vendor: Digikey; Vendor Part#: 311-4.7KJRCT-ND
R206 R306-R308 = RESISTOR: Mfg: Panasonic - ECG; Mfg Part#: ERJ-2GEJ221X; Package: 0402; RoHS Compliant?: Yes; Specifications: RES 220 OHM 1/10W 5% 0402 SMD
U5 U8 = KSZ8041NL: IC XCVR 10/100M EPHY IEEE 802.3u 3.3V QFN32; AGILE_PN: 312-79518; CAD_APPROVED: Yes; HEIGHT: 0.9MM; MFG_NAME01: Micrel; ROHS: Yes
C203 C216 C220 = CAP_NP: Mfg: Taiyo Yuden; Mfg Part#: LMK212BJ226MG-T; Oper. Temp. Range: -55°C ~ 85°C; Package: 0805; RoHS Compliant?: Yes; Specifications: CAP CER 22UF 10V X5R 0805
C204-C208 C214 C215 C217-C219 C221 C222 C225-C227 = CAP_NP: Mfg: Kemet; Mfg Part#: C0402C104K8PACTU; Package: 0402; RoHS Compliant?: Yes; Specifications: CAP .10UF 10V CERAMIC X5R 0402
C223 = CAP_NP: Mfg: Taiyo Yuden; Mfg Part#: EMK212B7475KG-T; Oper. Temp. Range: -55°C ~ 85°C; Package: 0805; RoHS Compliant?: Yes; Specifications: CAP CER 4.7UF 16V X7R 10% 0805
C224 = CAP_CaseE_1: Mfg: Kemet; Mfg Part#: B45197A2157K409; Oper. Temp. Range: -55°C ~ 85°C; Package: 7343-31 (EIA); Price @ 100 pcs: 0.014; Price @ 10K: 0.0060; Price @ 1K: 0.0066; RoHS Compliant?: Yes; Specifications: CAP TANT 150UF 10V 10% LOESR SMD; Vendor: Digikey; Vendor Part#: 399-3027-1-ND
D1-D3 = LED: Mfg: Lumex; Mfg Part#: SML-LX0603GW-TR; Package: 0603; RoHS Compliant?: Yes; Specifications: LED 565NM GRN DIFF 0603 SMD
D21 = DIODE_0: DIODE PWR RECT 2A 600V 403A-03; AGILE_PN: 480-77641; CAD_APPROVED: Yes; HEIGHT: 2.45MM; MFG_NAME01: ON SEMICONDUCTOR; MFG_PN01: MURS060T3G; ROHS: Yes; ROOM: POWER
J6 = Conn_USB-mini-ab_0: Mfg: Molex; Mfg Part#: 56579-0576; Package: 5-Pin USB conn; RoHS Compliant?: Yes; Specifications: CONN RECEPT USB 5POS RT ANG SMD
R233 = RESISTOR: Mfg: Yageo; Mfg Part#: RC0402JR-072KL; Oper. Temp. Range: -55°C ~ 85°C; Package: 0402; Price @ 100 pcs: 0.035; Price @ 10K: 0.002; Price @ 1K: 0.0138; RoHS Compliant?: Yes; Specifications: RES 2.0K OHM 1/16W 5% 0402 SMD; Vendor: Digikey; Vendor Part#: RC0402JR-072KL
R238 = RESISTOR: Mfg: Yageo; Mfg Part#: RC0402JR-071KL; Package: 0402; RoHS Compliant?: Yes; Specifications: RES 1.0K OHM 1/16W 5% 0402 SMD
R241 = RESISTOR: Mfg: Yageo; Mfg Part#: RC0402FR-0712KL; Package: 0402; RoHS Compliant?: Yes; Specifications: RES 12.0K OHM 1/16W 1% 0402 SMD
R242 = RESISTOR: Mfg: Yageo; Mfg Part#: RC0402FR-0722RL; Package: 0402; RoHS Compliant?: Yes; Specifications: RES 22.0 OHM 1/16W 1% 0402 SMD
R244 = RESISTOR: Mfg: Panasonic - ECG; Mfg Part#: ERJ-2RKF1003X; Mounting: NU; Package: 0402; RoHS Compliant?: Yes; Specifications: RES 100K OHM 1/10W 1% 0402 SMD
R245 = RESISTOR: Mfg: Yageo; Mfg Part#: RC0402JR-074K7L; Package: 0402; RoHS Compliant?: Yes; Specifications: RES 4.7K OHM 1/16W 5% 0402 SMD
R246 R247 R344 = RESISTOR: Mfg: Yageo; Mfg Part#: RC0402JR-07330RL; Package: 0402; RoHS Compliant?: Yes; Specifications: RES 330 OHM 1/16W 5% 0402 SMD
U24 = USB3300_4: Mfg: SMSC; Mfg Part#: USB3300-EZK; Package: QFN-32; RoHS Compliant?: Yes; Specifications: IC USB HOST/OTG PHY ULPI 32-QFN
U26 = MIC2505BM: Mfg: Micrel; Package: SOIC-8; RoHS Compliant?: Yes; Specifications: IC SW HIGH SIDE SGL 2A 8SOIC
U27-U29 = 74VHC1G00: Mfg: ON Semi; RoHS Compliant?: Yes; Specifications: IC GATE NAND SGL 2INPUT SOT353
U36 = SPB0503: DIODE TVS ARRAY 3CH -- 5V 0.225W SOT143; AGILE_PN: 480-76886; CAD_APPROVED: Yes; HEIGHT: 1.22MM; MFG_NAME01: LITTELFUSE; MFG_PN01: SP0503BAHTG; ROHS: Yes; ROOM: OSBDM
U1 = IC_CPU_MPC8309_1: Mfg: Freescale; Mfg Part#: MPC8309CVMAFDCA; Package: MAPBGA; Price @ 100 pcs: 10; Price @ 10K: 10; Price @ 1K: 10; RoHS Compliant?: Yes; Specifications: PowerQUICC II Pro Integrated Communications Processor; Vendor: Freescale; Vendor Part#: MPC8309CVMAFDCA

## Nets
+1.8V: C9.2 C11.2 C12.2 C13.2 C14.2 C15.2 C17.2 C18.2 C20.2 C21.2 C24.2 C25.2 C26.2 C27.2 C29.2 C31.2 C32.2 C33.2 C34.2 C36.2 C37.2 C38.2 C55.2 R41.1 U6.A1(VDD3) U6.A9(VDDQ9) U6.C1(VDDQ5) U6.C3(VDDQ4) U6.C7(VDDQ8) U6.C9(VDDQ1) U6.E1(VDD2) U6.E9(VDDQ2) U6.G1(VDDQ6) U6.G3(VDDQ7) U6.G7(VDDQ10) U6.G9(VDDQ3) U6.J1(VDDL) U6.J9(VDD4) U6.M9(VDD5) U6.R1(VDD1) U7.A1(VDD3) U7.A9(VDDQ9) U7.C1(VDDQ5) U7.C3(VDDQ4) U7.C7(VDDQ8) U7.C9(VDDQ1) U7.E1(VDD2) U7.E9(VDDQ2) U7.G1(VDDQ6) U7.G3(VDDQ7) U7.G7(VDDQ10) U7.G9(VDDQ3) U7.J1(VDDL) U7.J9(VDD4) U7.M9(VDD5) U7.R1(VDD1) ; also on sheet 1 4
+1.8V_VA1: C91.2 C92.2 U5.2(VDDPLL_1V8)
+1.8V_VA2: C93.2 C96.2 U8.2(VDDPLL_1V8)
+3.3V: C7.2 C22.2 C77.1 C78.2 C79.2 C98.2 C99.2 C203.1 C204.1 C205.1 C206.1 C207.1 C208.1 C209.1 C225.1 C226.1 C227.1 C255.2 C256.2 C322.1 C327.1 FB1.2 FB5.2 FB6.2 FB7.1 FB8.1 FB15.2 FB27.2 FB28.2 R9.2 R10.2 R11.2 R14.2 R15.2 R18.1 R25.2 R26.2 R27.2 R71.1 R89.1 R90.2 R166.1 R171.1 R174.1 R189.2 R190.2 R209.1 R211.1 R213.1 R222.2 R223.2 R226.2 R227.2 R228.2 R229.2 R233.1 R245.2 R246.1 R247.1 R249.1 R416.1 R417.1 R418.1 U4.4(VCC) U5.17(VDDIO_3V3) U8.17(VDDIO_3V3) U17.29(VIO) U17.43(VCC) U24.6(VDD1_3.3) U24.16(VDD2_3.3) U24.25(VDD4_3.3) U24.30(VDD3_3.3) U24.31(REG_EN) U27.5(VCC) U28.5(VCC) U29.5(VCC) U69.16(VCC) U72.5(VCC) ; also on sheet 1 2 4 5 11 12 13 14 15
+3.3VA2: C97.2 C119.1 C121.1 C251.2 FB8.2 J28.3(CT) J28.6(CT) U8.3(VDDA_3V3)
+5V: D21.2(ANODE) R244.1 U26.5(IN1) U26.7(IN2) ; also on sheet 1 5 11 12 15
AVCC_VCXO: C210.1 FB15.1 OSC4.6(VDD)
GND: C1.2 C7.1 C8.1 C9.1 C11.1 C12.1 C13.1 C14.1 C15.1 C16.2 C17.1 C18.1 C20.1 C21.1 C22.1 C24.1 C25.1 C26.1 C27.1 C29.1 C31.1 C32.1 C33.1 C34.1 C36.1 C37.1 C38.1 C39.1 C40.1 C56.1 C57.1 C77.2 C78.1 C79.1 C91.1 C92.1 C93.1 C94.1 C95.1 C96.1 C97.1 C98.1 C99.1 C100.1 C101.1 C102.2 C103.1 C104.2 C116.2 C117.1 C118.1 C119.2 C120.1 C121.2 C203.2 C204.2 C205.2 C206.2 C207.2 C208.2 C209.2 C210.2 C214.2 C215.2 C216.2 C217.2 C218.2 C219.2 C220.2 C221.2 C222.2 C223.2 C224.2 C225.2 C226.2 C227.2 C251.1 C255.1 C256.1 C259.2 C322.2 C327.2 D1.2(CATHODE) FB13.2 FB14.2 FB17.1 FB21.1 J28.4(GND) J28.5(GND) J29.4(GND) J29.5(GND) OSC1.2(C_GND) OSC2.2(C_GND) OSC4.3(GND) R21.2 R42.2 R155.2 R167.2 R172.2 R175.2 R186.2 R187.2 R188.2 R191.2 R192.2 R208.2 R210.2 R212.2 R214.2 R219.2 R220.2 R221.2 R224.2 R225.2 R231.2 R238.1 R241.2 R252.2 R429.2 R430.2 R431.2 S1.1 S2.1 U1.C6(TEST_MODE) U1.P23(SYS_XTAL_IN) U1.V23(RTC_PIT_CLOCK) U4.1(GND) U5.1(GND) U5.33(PAD) U6.A3(VSS2) U6.A7(VSSQ6) U6.B2(VSSQ5) U6.B8(VSSQ9) U6.D2(VSSQ3) U6.D8(VSSQ7) U6.E3(VSS3) U6.E7(VSSQ10) U6.F2(VSSQ4) U6.F8(VSSQ8) U6.H2(VSSQ2) U6.H8(VSSQ1) U6.J3(VSS4) U6.J7(VSSDL) U6.N1(VSS5) U6.P9(VSS1) U7.A3(VSS2) U7.A7(VSSQ6) U7.B2(VSSQ5) U7.B8(VSSQ9) U7.D2(VSSQ3) U7.D8(VSSQ7) U7.E3(VSS3) U7.E7(VSSQ10) U7.F2(VSSQ4) U7.F8(VSSQ8) U7.H2(VSSQ2) U7.H8(VSSQ1) U7.J3(VSS4) U7.J7(VSSDL) U7.N1(VSS5) U7.P9(VSS1) U8.1(GND) U8.33(PAD) U17.33(VSS1) U17.52(VSS2) U18.6(GND) U24.1(GND1) U24.2(GND2) U24.33(PAD) U26.3(GND) U27.3(GND) U28.3(GND) U29.3(GND) U36.1(ANODE) U69.2(S1A) U69.5(S1B) U69.8(GND) U69.11(S1C) U69.14(S1D) U72.2(GND) ; also on sheet 1 2 4 5 6 11 12 13 14 15
GND_EARTH: C116.1 C259.1 FB13.1 FB14.1 FB21.2 J6.6 J6.7 J6.8 J6.9 J28.CG1(GND1) J28.CG2(GND2) J29.CG1(GND1) J29.CG2(GND2) ; also on sheet 5
CF_CLK_IN: R40.2 ; also on sheet 15
CF_VOCOX: OSC4.1(V_CTRL) ; also on sheet 6 15
CFG_CLKIN_DIVB: R18.2 R21.1 U1.U23(CFG_CLKIN_DIV_B)
ETH2_RXN: J28.8(RD-) R218.2 U8.4(RX-)
ETH2_RXP: J28.7(RD+) R217.2 U8.5(RX+)
ETH2_TXN: J28.2(TD-) R216.2 U8.6(TX-)
ETH2_TXP: J28.1(TD+) R215.2 U8.7(TX+)
ETH_CT1: C94.2 C95.2 C102.1 C104.1 FB7.2 J29.3(CT) J29.6(CT) U5.3(VDDA_3V3)
ETH_RXN: J29.8(RD-) R176.2 U5.4(RX-)
ETH_RXP: J29.7(RD+) R173.2 U5.5(RX+)
ETH_TXN: J29.2(TD-) R169.2 U5.6(TX-)
ETH_TXP: J29.1(TD+) R164.2 U5.7(TX+)
FEC1_INT#: U5.21(INTRP) ; also on sheet 13
FEC1_PHY_CLK_25MHz: U5.9(XI/REFCLK) ; also on sheet 14
FEC2_INT#: U8.21(INTRP) ; also on sheet 13
FEC2_PHY_CLK_25MHz: U8.9(XI/REFCLK) ; also on sheet 14
MPC_DDR_A0: U1.L3(MEMC_MA0) U6.M8(A0) U7.M8(A0)
MPC_DDR_A1: U1.L5(MEMC_MA1) U6.M3(A1) U7.M3(A1)
MPC_DDR_A2: U1.L2(MEMC_MA2) U6.M7(A2) U7.M7(A2)
MPC_DDR_A3: U1.L1(MEMC_MA3) U6.N2(A3) U7.N2(A3)
MPC_DDR_A4: U1.M3(MEMC_MA4) U6.N8(A4) U7.N8(A4)
MPC_DDR_A5: U1.M4(MEMC_MA5) U6.N3(A5) U7.N3(A5)
MPC_DDR_A6: U1.M1(MEMC_MA6) U6.N7(A6) U7.N7(A6)
MPC_DDR_A7: U1.N1(MEMC_MA7) U6.P2(A7) U7.P2(A7)
MPC_DDR_A8: U1.N2(MEMC_MA8) U6.P8(A8) U7.P8(A8)
MPC_DDR_A9: U1.N3(MEMC_MA9) U6.P3(A9) U7.P3(A9)
MPC_DDR_A10: U1.L4(MEMC_MA10) U6.M2(A10) U7.M2(A10)
MPC_DDR_A11: U1.P2(MEMC_MA11) U6.P7(A11) U7.P7(A11)
MPC_DDR_A12: U1.N4(MEMC_MA12) U6.R2(A12) U7.R2(A12)
MPC_DDR_A13: U1.P1(MEMC_MA13) U6.R3(RFU1) U7.R3(RFU1)
MPC_DDR_BA0: U1.K2(MEMC_MBA0) U6.L2(BA0) U7.L2(BA0)
MPC_DDR_BA1: U1.K3(MEMC_MBA1) U6.L3(BA1) U7.L3(BA1)
MPC_DDR_BA2: U1.N5(MEMC_MBA2) U6.L1(BA2) U7.L1(BA2)
MPC_DDR_CAS#: U1.J3(MEMC_MCAS_B) U6.L7(CAS#) U7.L7(CAS#)
MPC_DDR_CK1: R36.1 U1.R1(MEMC_MCK0) U7.J8(CK)
MPC_DDR_CK1#: R36.2 U1.T1(MEMC_MCK_B0) U7.K8(CK#)
MPC_DDR_CK2: R37.1 U1.R3(MEMC_MCK1) U6.J8(CK)
MPC_DDR_CK2#: R37.2 U1.P3(MEMC_MCK_B1) U6.K8(CK#)
MPC_DDR_CKE: U1.P4(MEMC_MCKE) U6.K2(CKE) U7.K2(CKE)
MPC_DDR_CS0#: U1.J4(MEMC_MCS_B0) U6.L8(CS#) U7.L8(CS#)
MPC_DDR_D0: U1.U5(MEMC_MDQ0) U7.H1(DQ4)
MPC_DDR_D1: U1.AA1(MEMC_MDQ1) U7.G8(DQ0)
MPC_DDR_D2: U1.W3(MEMC_MDQ2) U7.F9(DQ7)
MPC_DDR_D3: U1.R5(MEMC_MDQ3) U7.F1(DQ6)
MPC_DDR_D4: U1.W2(MEMC_MDQ4) U7.H7(DQ2)
MPC_DDR_D5: U1.U3(MEMC_MDQ5) U7.H9(DQ5)
MPC_DDR_D6: U1.U2(MEMC_MDQ6) U7.G2(DQ1)
MPC_DDR_D7: U1.T3(MEMC_MDQ7) U7.H3(DQ3)
MPC_DDR_D8: U1.H3(MEMC_MDQ8) U6.H9(DQ5)
MPC_DDR_D9: U1.H4(MEMC_MDQ9) U6.G8(DQ0)
MPC_DDR_D10: U1.G3(MEMC_MDQ10) U6.H7(DQ2)
MPC_DDR_D11: U1.F3(MEMC_MDQ11) U6.H1(DQ4)
MPC_DDR_D12: U1.G5(MEMC_MDQ12) U6.F9(DQ7)
MPC_DDR_D13: U1.F4(MEMC_MDQ13) U6.F1(DQ6)
MPC_DDR_D14: U1.F5(MEMC_MDQ14) U6.H3(DQ3)
MPC_DDR_D15: U1.E3(MEMC_MDQ15) U6.G2(DQ1)
MPC_DDR_D16: U1.V4(MEMC_MDQ16) U7.B9(DQ15)
MPC_DDR_D17: U1.Y2(MEMC_MDQ17) U7.D7(DQ10)
MPC_DDR_D18: U1.Y1(MEMC_MDQ18) U7.C8(DQ8)
MPC_DDR_D19: U1.U4(MEMC_MDQ19) U7.D9(DQ13)
MPC_DDR_D20: U1.V1(MEMC_MDQ20) U7.B1(DQ14)
MPC_DDR_D21: U1.R4(MEMC_MDQ21) U7.C2(DQ9)
MPC_DDR_D22: U1.U1(MEMC_MDQ22) U7.D3(DQ11)
MPC_DDR_D23: U1.T2(MEMC_MDQ23) U7.D1(DQ12)
MPC_DDR_D24: U1.J5(MEMC_MDQ24) U6.D9(DQ13)
MPC_DDR_D25: U1.G2(MEMC_MDQ25) U6.B9(DQ15)
MPC_DDR_D26: U1.G1(MEMC_MDQ26) U6.C8(DQ8)
MPC_DDR_D27: U1.F1(MEMC_MDQ27) U6.D3(DQ11)
MPC_DDR_D28: U1.E2(MEMC_MDQ28) U6.D7(DQ10)
MPC_DDR_D29: U1.D2(MEMC_MDQ29) U6.C2(DQ9)
MPC_DDR_D30: U1.C2(MEMC_MDQ30) U6.D1(DQ12)
MPC_DDR_D31: U1.C1(MEMC_MDQ31) U6.B1(DQ14)
MPC_DDR_DM0: U1.W1(MEMC_MDM0) U7.F3(LDM)
MPC_DDR_DM1: U1.E1(MEMC_MDM1) U6.F3(LDM)
MPC_DDR_DM2: U1.V3(MEMC_MDM2) U7.B3(UDM)
MPC_DDR_DM3: U1.D1(MEMC_MDM3) U6.B3(UDM)
MPC_DDR_DM8: U1.W5(MEMC_MDM8)
MPC_DDR_DQS0: U1.T5(MEMC_MDQS0) U7.F7(LDQS)
MPC_DDR_DQS1: U1.H5(MEMC_MDQS1) U6.F7(LDQS)
MPC_DDR_DQS2: U1.P5(MEMC_MDQS2) U7.B7(UDQS)
MPC_DDR_DQS3: U1.E5(MEMC_MDQS3) U6.B7(UDQS)
MPC_DDR_DQS8: U1.V5(MEMC_M_DQS8)
MPC_DDR_ECC0: U1.Y5(MEMC_MECC0)
MPC_DDR_ECC1: U1.AA4(MEMC_MECC1)
MPC_DDR_ECC2: U1.Y4(MEMC_MECC2)
MPC_DDR_ECC3: U1.AA3(MEMC_MECC3)
MPC_DDR_ECC4: U1.AC2(MEMC_MECC4)
MPC_DDR_ECC5: U1.AB2(MEMC_MECC5)
MPC_DDR_ECC6: U1.Y3(MEMC_MECC6)
MPC_DDR_ECC7: U1.AB1(MEMC_MECC7)
MPC_DDR_ODT0: U1.H1(MEMC_MODT0) U6.K9(ODT) U7.K9(ODT)
MPC_DDR_RAS#: U1.K1(MEMC_MRAS_B) U6.K7(RAS#) U7.K7(RAS#)
MPC_DDR_VREF: C39.2 C40.2 C55.1 C56.2 C57.2 R41.2 R42.1 U1.M6(MEMC_MVREF) U6.J2(VREF) U7.J2(VREF)
MPC_DDR_WE#: U1.J1(MEMC_MWE_B) U6.K3(WE#) U7.K3(WE#)
MPC_FEC1_COL: R142.2 ; also on sheet 14
MPC_FEC1_CRS: R145.2 ; also on sheet 14
MPC_FEC1_RXCLK: R135.1 ; also on sheet 14
MPC_FEC1_RXD0: R128.1 ; also on sheet 14
MPC_FEC1_RXD1: R129.1 ; also on sheet 14
MPC_FEC1_RXD2: R130.1 ; also on sheet 14
MPC_FEC1_RXD3: R131.1 ; also on sheet 14
MPC_FEC1_RXDV: R133.1 ; also on sheet 14
MPC_FEC1_RXER: R136.1 ; also on sheet 14
MPC_FEC1_TXCLK: R154.1 ; also on sheet 14
MPC_FEC1_TXD0: U5.24(TXDO/TXD[0]) ; also on sheet 14
MPC_FEC1_TXD1: U5.25(TXD1/TXD[1]) ; also on sheet 14
MPC_FEC1_TXD2: U5.26(TXD2) ; also on sheet 14
MPC_FEC1_TXD3: U5.27(TXD3) ; also on sheet 14
MPC_FEC1_TXEN: U5.23(TXEN/TX_EN) ; also on sheet 14
MPC_FEC2_COL: R204.2 ; also on sheet 14
MPC_FEC2_CRS: R205.2 ; also on sheet 14
MPC_FEC2_RXCLK: R202.1 ; also on sheet 14
MPC_FEC2_RXD0: R197.1 ; also on sheet 14
MPC_FEC2_RXD1: R198.1 ; also on sheet 14
MPC_FEC2_RXD2: R199.1 ; also on sheet 14
MPC_FEC2_RXD3: R200.1 ; also on sheet 14
MPC_FEC2_RXDV: R201.1 ; also on sheet 14
MPC_FEC2_RXER: R203.1 ; also on sheet 14
MPC_FEC2_TXCLK: R207.1 ; also on sheet 14
MPC_FEC2_TXD0: U8.24(TXDO/TXD[0]) ; also on sheet 14
MPC_FEC2_TXD1: U8.25(TXD1/TXD[1]) ; also on sheet 14
MPC_FEC2_TXD2: U8.26(TXD2) ; also on sheet 14
MPC_FEC2_TXD3: U8.27(TXD3) ; also on sheet 14
MPC_FEC2_TXEN: U8.23(TXEN/TX_EN) ; also on sheet 14
MPC_FEC_MDC: U5.12(MDC) U8.12(MDC) ; also on sheet 6 14
MPC_FEC_MDIO: U5.11(MDIO) U8.11(MDIO) ; also on sheet 6 14
MPC_HDLC1_RTS#_BOOT_CFG1: U69.7(DB) ; also on sheet 6 12
MPC_HDLC1_TXD_BOOT_CFG0: U69.4(DA) ; also on sheet 6 12
MPC_HDLC2_RTS#_BOOT_CFG3: U69.12(DD) ; also on sheet 6 12
MPC_HDLC2_TXD_BOOT_CFG2: U69.9(DC) ; also on sheet 6 12
MPC_HRESET#: U1.W23(HRESET_B) U5.32(RST#) U8.32(RST#) U69.15(\\~{E}N) ; also on sheet 5 6 15
MPC_JTAG_TCK: R9.1 U1.A2(TCK) ; also on sheet 15
MPC_JTAG_TDI: R10.1 U1.C5(TDI) ; also on sheet 15
MPC_JTAG_TDO: R11.1 U1.A3(TDO) ; also on sheet 15
MPC_JTAG_TMS: R14.1 U1.D7(TMS) ; also on sheet 15
MPC_JTAG_TRST#: R15.1 U1.E9(TRST_B) ; also on sheet 15
MPC_LBC_ADD1: U17.1(A23) ; also on sheet 6 13
MPC_LBC_ADD2: U17.2(A22) ; also on sheet 6 13
MPC_LBC_ADD3: U17.15(A21) ; also on sheet 6 13
MPC_LBC_ADD4: U17.12(A20) ; also on sheet 6 13
MPC_LBC_ADD5: U17.11(A19) ; also on sheet 6 13
MPC_LBC_ADD6: U17.18(A18) ; also on sheet 6 13
MPC_LBC_ADD7: U17.19(A17) ; also on sheet 6 13
MPC_LBC_ADD8: U17.54(A16) ; also on sheet 6 13
MPC_LBC_ADD9: U17.3(A15) ; also on sheet 6 13
MPC_LBC_ADD10: U17.4(A14) ; also on sheet 6 13
MPC_LBC_ADD11: U17.5(A13) ; also on sheet 6 13
MPC_LBC_ADD12: U17.6(A12) ; also on sheet 6 13
MPC_LBC_ADD13: U17.7(A11) ; also on sheet 6 13
MPC_LBC_ADD14: U17.8(A10) ; also on sheet 6 13
MPC_LBC_ADD15: U17.9(A9) ; also on sheet 6 13
MPC_LBC_ADD16: U17.10(A8) ; also on sheet 6 13
MPC_LBC_ADD17: U17.20(A7) ; also on sheet 6 13
MPC_LBC_ADD18: U17.21(A6) ; also on sheet 6 13
MPC_LBC_ADD19: U17.22(A5) ; also on sheet 6 13
MPC_LBC_ADD20: U17.23(A4) ; also on sheet 6 13
MPC_LBC_ADD21: U17.24(A3) ; also on sheet 6 13
MPC_LBC_ADD22: U17.25(A2) ; also on sheet 6 13
MPC_LBC_ADD23: U17.26(A1) ; also on sheet 6 13
MPC_LBC_ADD24: U17.31(A0) ; also on sheet 5 6 13
MPC_LBC_CS0#: U72.3(I0) ; also on sheet 6 13
MPC_LBC_LAD0: U17.51(DQ15/A-1) ; also on sheet 13
MPC_LBC_LAD1: U17.49(DQ14) ; also on sheet 13
MPC_LBC_LAD2: U17.47(DQ13) ; also on sheet 13
MPC_LBC_LAD3: U17.45(DQ12) ; also on sheet 13
MPC_LBC_LAD4: U17.42(DQ11) ; also on sheet 13
MPC_LBC_LAD5: U17.40(DQ10) ; also on sheet 13
MPC_LBC_LAD6: U17.38(DQ9) ; also on sheet 13
MPC_LBC_LAD7: U17.36(DQ8) ; also on sheet 13
MPC_LBC_LAD8: U17.50(DQ7) ; also on sheet 13
MPC_LBC_LAD9: U17.48(DQ6) ; also on sheet 13
MPC_LBC_LAD10: U17.46(DQ5) ; also on sheet 13
MPC_LBC_LAD11: U17.44(DQ4) ; also on sheet 13
MPC_LBC_LAD12: U17.41(DQ3) ; also on sheet 13
MPC_LBC_LAD13: U17.39(DQ2) ; also on sheet 13
MPC_LBC_LAD14: U17.37(DQ1) ; also on sheet 13
MPC_LBC_LAD15: U17.35(DQ0) ; also on sheet 13
MPC_LBC_RE/OE#: U17.34(~{OE}) ; also on sheet 6 13
MPC_LBC_WE0#: U17.13(~{WE}) ; also on sheet 5 6 13
MPC_POR#: R26.1 U1.W22(PORESET_B) U4.2(RESET#) U17.14(~{RESET}) ; also on sheet 15
MPC_QE_CLK_IN: R35.2 U1.R22(QE_CLK_IN) ; also on sheet 6
MPC_TMR_CLK: R239.2 TP5.1(TP) ; also on sheet 14
MPC_USB_D0: U1.Y6(USBDR_TXDRXD0/GPIO_32/QE_TRB_O) U24.24(DATA0)
MPC_USB_D1: U1.W9(USBDR_TXDRXD1/GPIO_33/QE_TRB_I) U24.23(DATA1)
MPC_USB_D2: U1.AB5(USBDR_TXDRXD2/GPIO_34/QE_BRG_1) U24.22(DATA2)
MPC_USB_D3: U1.AA5(USBDR_TXDRXD3/GPIO_35/QE_BRG_2) U24.21(DATA3)
MPC_USB_D4: U1.Y8(USBDR_TXDRXD4/GPIO_36/QE_BRG_3) U24.20(DATA4)
MPC_USB_D5: U1.AC4(USBDR_TXDRXD5/GPIO_37/QE_BRG_4) U24.19(DATA5)
MPC_USB_D6: U1.AC3(USBDR_TXDRXD6/GPIO_38/QE_BRG_9) U24.18(DATA6)
MPC_USB_D7: U1.AB3(USBDR_TXDRXD7/GPIO_39/QE_BRG_11) U24.17(DATA7)
MPC_USB_DIR: R227.1 U1.AA7(USBDR_DIR/URM_TRIG/) U24.12(DIR)
MPC_USB_NXT: R228.1 U1.AC5(USBDR_NXT/UART2_SIN1/UC1_REQ_4) U24.11(NXT)
MPC_USB_PCTL0: R233.2 TP9.1(TP) U1.W8(USBDR_PCTL0/UART2_SOUT1/UC2_URM/LB_P_OR_CFG_BOOT_ECC) U29.1(I0) U29.2(I1)
MPC_USB_PCTL1: TP8.1(TP) U1.W7(USBDR_PCTL1/UART2_SOUT2/UART2_RTS_B1/_LB_POR_BOOT_ERR) U28.1(I0) U28.2(I1)
MPC_USB_STP: R229.1 U1.W6(USBDR_STP/UC3_URM/QE_EXT_REQ_2) U24.13(STP)
NOR_FLASH_CS#: U17.32(~{CE}) U72.4(Y) ; also on sheet 13
OB_BOOT: U69.1(IN) U72.6(S) ; also on sheet 13
OB_BOOT_CONFIG0: R416.2 R429.1 U69.3(S2A) ; also on sheet 6
OB_BOOT_CONFIG1: R249.2 R252.1 U69.6(S2B) ; also on sheet 6
OB_BOOT_CONFIG2: R417.2 R430.1 U69.10(S2C) ; also on sheet 6
OB_BOOT_CONFIG3: R418.2 R431.1 U69.13(S2D) ; also on sheet 6
OB_DRV_NOR_LCS#: R27.1 U72.1(I1) ; also on sheet 6
PHY2_ADD0: R200.2 R209.2 R210.1 U8.13(RXD3/PHYAD0)
PHY2_ADD1: R199.2 R211.2 R212.1 U8.14(RXD2/PHYAD1)
PHY2_ADD2: R198.2 R213.2 R214.1 U8.15(RXD1/RXD[1]/PHYAD2)
PHY2_CFG0: R204.1 R219.1 U8.28(COL/CONFIG0)
PHY2_CFG1: R205.1 R220.1 U8.29(CRS/CONFIG1)
PHY2_CFG2: R201.2 R221.1 U8.18(RXDV/CRSDV/CONFIG2)
PHY2_DUP: R197.2 R224.1 U8.16(RXD0/RXD[0]/DUPLEX)
PHY2_ISO: R203.2 R225.1 U8.20(RXER/RX_ER/ISO)
PHY2_LED0: R222.1 R306.2 U8.30(LED0/NWAYEN)
PHY2_LED1: R206.2 R223.1 U8.31(LED1/SPEED)
PHY_ADD0: R131.2 R166.2 R167.1 U5.13(RXD3/PHYAD0)
PHY_ADD1: R130.2 R171.2 R172.1 U5.14(RXD2/PHYAD1)
PHY_ADD2: R129.2 R174.2 R175.1 U5.15(RXD1/RXD[1]/PHYAD2)
PHY_CFG0: R142.1 R186.1 U5.28(COL/CONFIG0)
PHY_CFG1: R145.1 R187.1 U5.29(CRS/CONFIG1)
PHY_CFG2: R133.2 R188.1 U5.18(RXDV/CRSDV/CONFIG2)
PHY_DUP: R128.2 R191.1 U5.16(RXD0/RXD[0]/DUPLEX)
PHY_ISO: R136.2 R192.1 U5.20(RXER/RX_ER/ISO)
PHY_LED0: R189.1 R308.2 U5.30(LED0/NWAYEN)
PHY_LED1: R190.1 R307.2 U5.31(LED1/SPEED)
QUIESCE#: U1.D6(QUIESCE_B)
REXT: C100.2 R155.1 U5.10(REXT)
REXT2: C117.2 R208.1 U8.10(REXT)
SWPB_2_MPC_IRQ#: S2.2 ; also on sheet 13
SYS_MCLK: R31.2 ; also on sheet 2
SYSCLK: R12.2 U1.R23(SYS_CLK_IN)
THERM0: U1.E8(THERM0) ; also on sheet 6
USB_CLKIN: R34.2 U24.28(XI)
USB_CLKOUT: R226.1 R242.1 U1.AC9(USBDR_CLK/UART2_SIN2/UART2_CTS_B1/)
USB_CPEN: U24.3(CPEN) U26.1(CTL)
USB_DN: J6.2 U24.8(DM) U36.2(CATHODE1)
USB_DP: J6.3 U24.7(DP) U36.3(CATHODE2)
USB_ID: J6.4 U24.5(ID)
USB_INT#: R245.1 TP6.1(TP) U24.10(VBUS_DT) U26.2(FLG) U27.1(I0) U27.2(I1) ; also on sheet 13
USB_PWRFAULT: R231.1 TP7.1(TP) U1.AA6(USBDR_PWRFAULT/CE_PIO_1/) U27.4(O)
USB_VBUS: C221.1 C222.1 C223.1 C224.1 FB16.2 R244.2 R344.2 U24.4(VBUS) U26.6(OUT1) U26.8(OUT2)
N21635092: C118.2 R215.1 R216.1
N21635138: C120.2 R217.1 R218.1
N23644757: C1.1 FB1.1 OSC1.4(VCC) R1.2
N23652818: OSC1.1(TRI_STATE) R1.1
N23994969: R25.1 S1.2 U4.3(MR#)
N32686119: OSC1.3(OUT) R12.1
N34312629: R202.2 U8.19(RXC)
N34322264: R207.2 U8.22(TXC)
N35213355: FB27.1 J28.9(YA) J28.12(GA)
N35224058: J28.10(YC) R206.1
N35225449: J28.11(GC) R306.1
N39629006: C8.2 FB5.1 U18.7(VDD) U18.8(OE)
N39629020: R31.1 U18.2(Q1)
N39629058: C16.1 FB6.1 OSC2.4(VCC) R33.2
N39629086: OSC2.1(TRI_STATE) R33.1
N39629134: OSC2.3(OUT) R32.1
N39629136: R35.1 U18.4(Q3)
N39629138: R40.1 U18.5(Q4)
N39629148: R32.2 U18.1(ICLK)
N39629190: R34.1 U18.3(Q2)
N40988324: R89.2 U17.17(RY/~{BY})
N40988461: R90.1 U17.53(~{BYTE})
N40988483: R71.2 U17.16(VPP/WP#)
N41249546: J29.10(YC) R307.1
N41249592: J29.11(GC) R308.1
N41249605: FB28.1 J29.9(YA) J29.12(GA)
N41249671: C101.2 R164.1 R169.1
N41249707: C103.2 R173.1 R176.1
N41249787: R135.2 U5.19(RXC)
N41249950: R154.2 U5.22(TXC)
N41434727: R238.2 U24.9(RST)
N41434771: D1.1(ANODE) R344.1
N41434896: R242.2 U24.14(CLKOUT)
N41434966: C214.1 C215.1 C220.1 U24.15(VDD1_1.8) U24.26(VDD1.8)
N41434993: D21.1(CATHODE) FB16.1 J6.1 U36.4(CATHODE3)
N41434995: C216.1 C217.1 C218.1 C219.1 U24.29(VDDA1.8)
N41435058: R241.1 U24.32(RBIAS)
N41435062: D3.2(CATHODE) U29.4(O)
N41435139: D2.2(CATHODE) U28.4(O)
N42133966: OSC4.4(OUT) R239.1
N42743247: FB17.2 J6.5
N45681385: D2.1(ANODE) R246.2
N45681388: D3.1(ANODE) R247.2

Not connected (* = marked no-connect by the designer): OSC4 2(INH#)* 5(NC)*; U1 H2(MEMC_MODT1)* K5(MEMC_MCS_B1)* P19(SYS_XTAL_OUT)*; U5 8(XO)*; U6 A2(NC2)* A8(UDQS#_/_NU1)* E2(NC3)* E8(LDQS_/_NU2)* R7(RFU3)* R8(NC1)*; U7 A2(NC2)* A8(UDQS#_/_NU1)* E2(NC3)* E8(LDQS_/_NU2)* R7(RFU3)* R8(NC1)*; U8 8(XO)*; U17 27(NC1)* 28(NC2)* 30(NC3)* 55(NC4)* 56(NC5)*; U24 27(XO); U26 4(GATE)*

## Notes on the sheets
sheet 7
- 10/100 RJ45 with Magnetics
- 10/100 ETHERNET PHY
- PHY BOOT STRAPS
- PHY ADDRESS[4:0]=>0X00001
- PHY ADD0
- PHY ADD1
- PHY ADD2
- CONFIG[0:2]=>000  MII
- NWAYEN=>Auto Nego Enable(default)
  SPEED=>100Mbps(default)
  DUPLEX=>FULL DUPLEX
  ISO => PHY not in Isolate mode (Default)
- NWAYEN
- SPEED
- DUPLEX
- LED0 = LINK/ACT
  LED1 = SPEED
- ISO
- LED Mode
- LED #
- [00]
- [01]
- LED0
- LINK/ACT
- LINK
- LED1
- SPEED
- SPEED
- Note:
  Software: Configure LED mode for [00] setting
- 10/100 RJ45 with Magnetics
- PHY BOOT STRAPS
- 10/100 ETHERNET PHY
- PHY ADDRESS[4:0]=>0X00010
- PHY ADD0
- PHY ADD1
- PHY ADD2
- CONFIG[0:2]=>000  MII
- LED0 = LINK/ACT
  LED1 = SPEED
- NWAYEN=>Auto Nego Enable(default)
  SPEED=>100Mbps(default)
  DUPLEX=>FULL DUPLEX
  ISO => PHY not in Isolate mode (Default)
- LED Mode
- LED #
- [00]
- [01]
- NWAYEN
- LED0
- LINK/ACT
- LINK
- SPEED
- DUPLEX
- LED1
- SPEED
- SPEED
- ISO
- Note:
  Software: Configure LED mode for [00] setting
sheet 8
- MPC RESET, CLOCK & Switch
- IEEE1588 Clock Generation
- Reset Configuration Words Source
- CFG_RESET
- DESCRIPTION
- SOURCE[0:3]
- MPC Boot MUX
- 0000
- RCW from eLBC NOR (Default )
- 0001
- RCW from eLBC NAND (small page 8-bit)
- 0010
- Reserved
- 0011
- Reserved
- 0100
- RCW from I2C
- 0101
- RCW from eLBC NAND (large page 8-bit)
- 0110
- Reserved
- 0111
- Reserved
- 1000
- RCW hard-coded, boot from eLBC
- 1001
- RCW hard-coded, boot from eLBC
- When IN=0, D=S1
  Boot from on board NOR flash
  When IN=1, D=S2
  Boot from SD card
- 1010
- RCW hard-coded, boot from eLBC
- 1011
- RCW from eLBC NOR
- 1100
- RCW hard-coded, boot from eLBC
- 1101
- RCW hard-coded, boot from eSDHC (OB_BOOT default)
- 1110
- RCW hard-coded, boot from eSDHC
- 1111
- RCW hard-coded, boot from SPI
- When S=0,
  CS0# = ON BOARD FLASH CS
  When S=1
  CS0# = OFF BOARD CS
sheet 9
- USB Interface
- USB PHY
- Mini USB AB
sheet 10
- DDR2 Memory
- NOR FLASH
